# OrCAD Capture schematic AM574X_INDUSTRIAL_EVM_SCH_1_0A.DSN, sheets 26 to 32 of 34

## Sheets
26 Pg17: Gbit Ethernet #0: size C
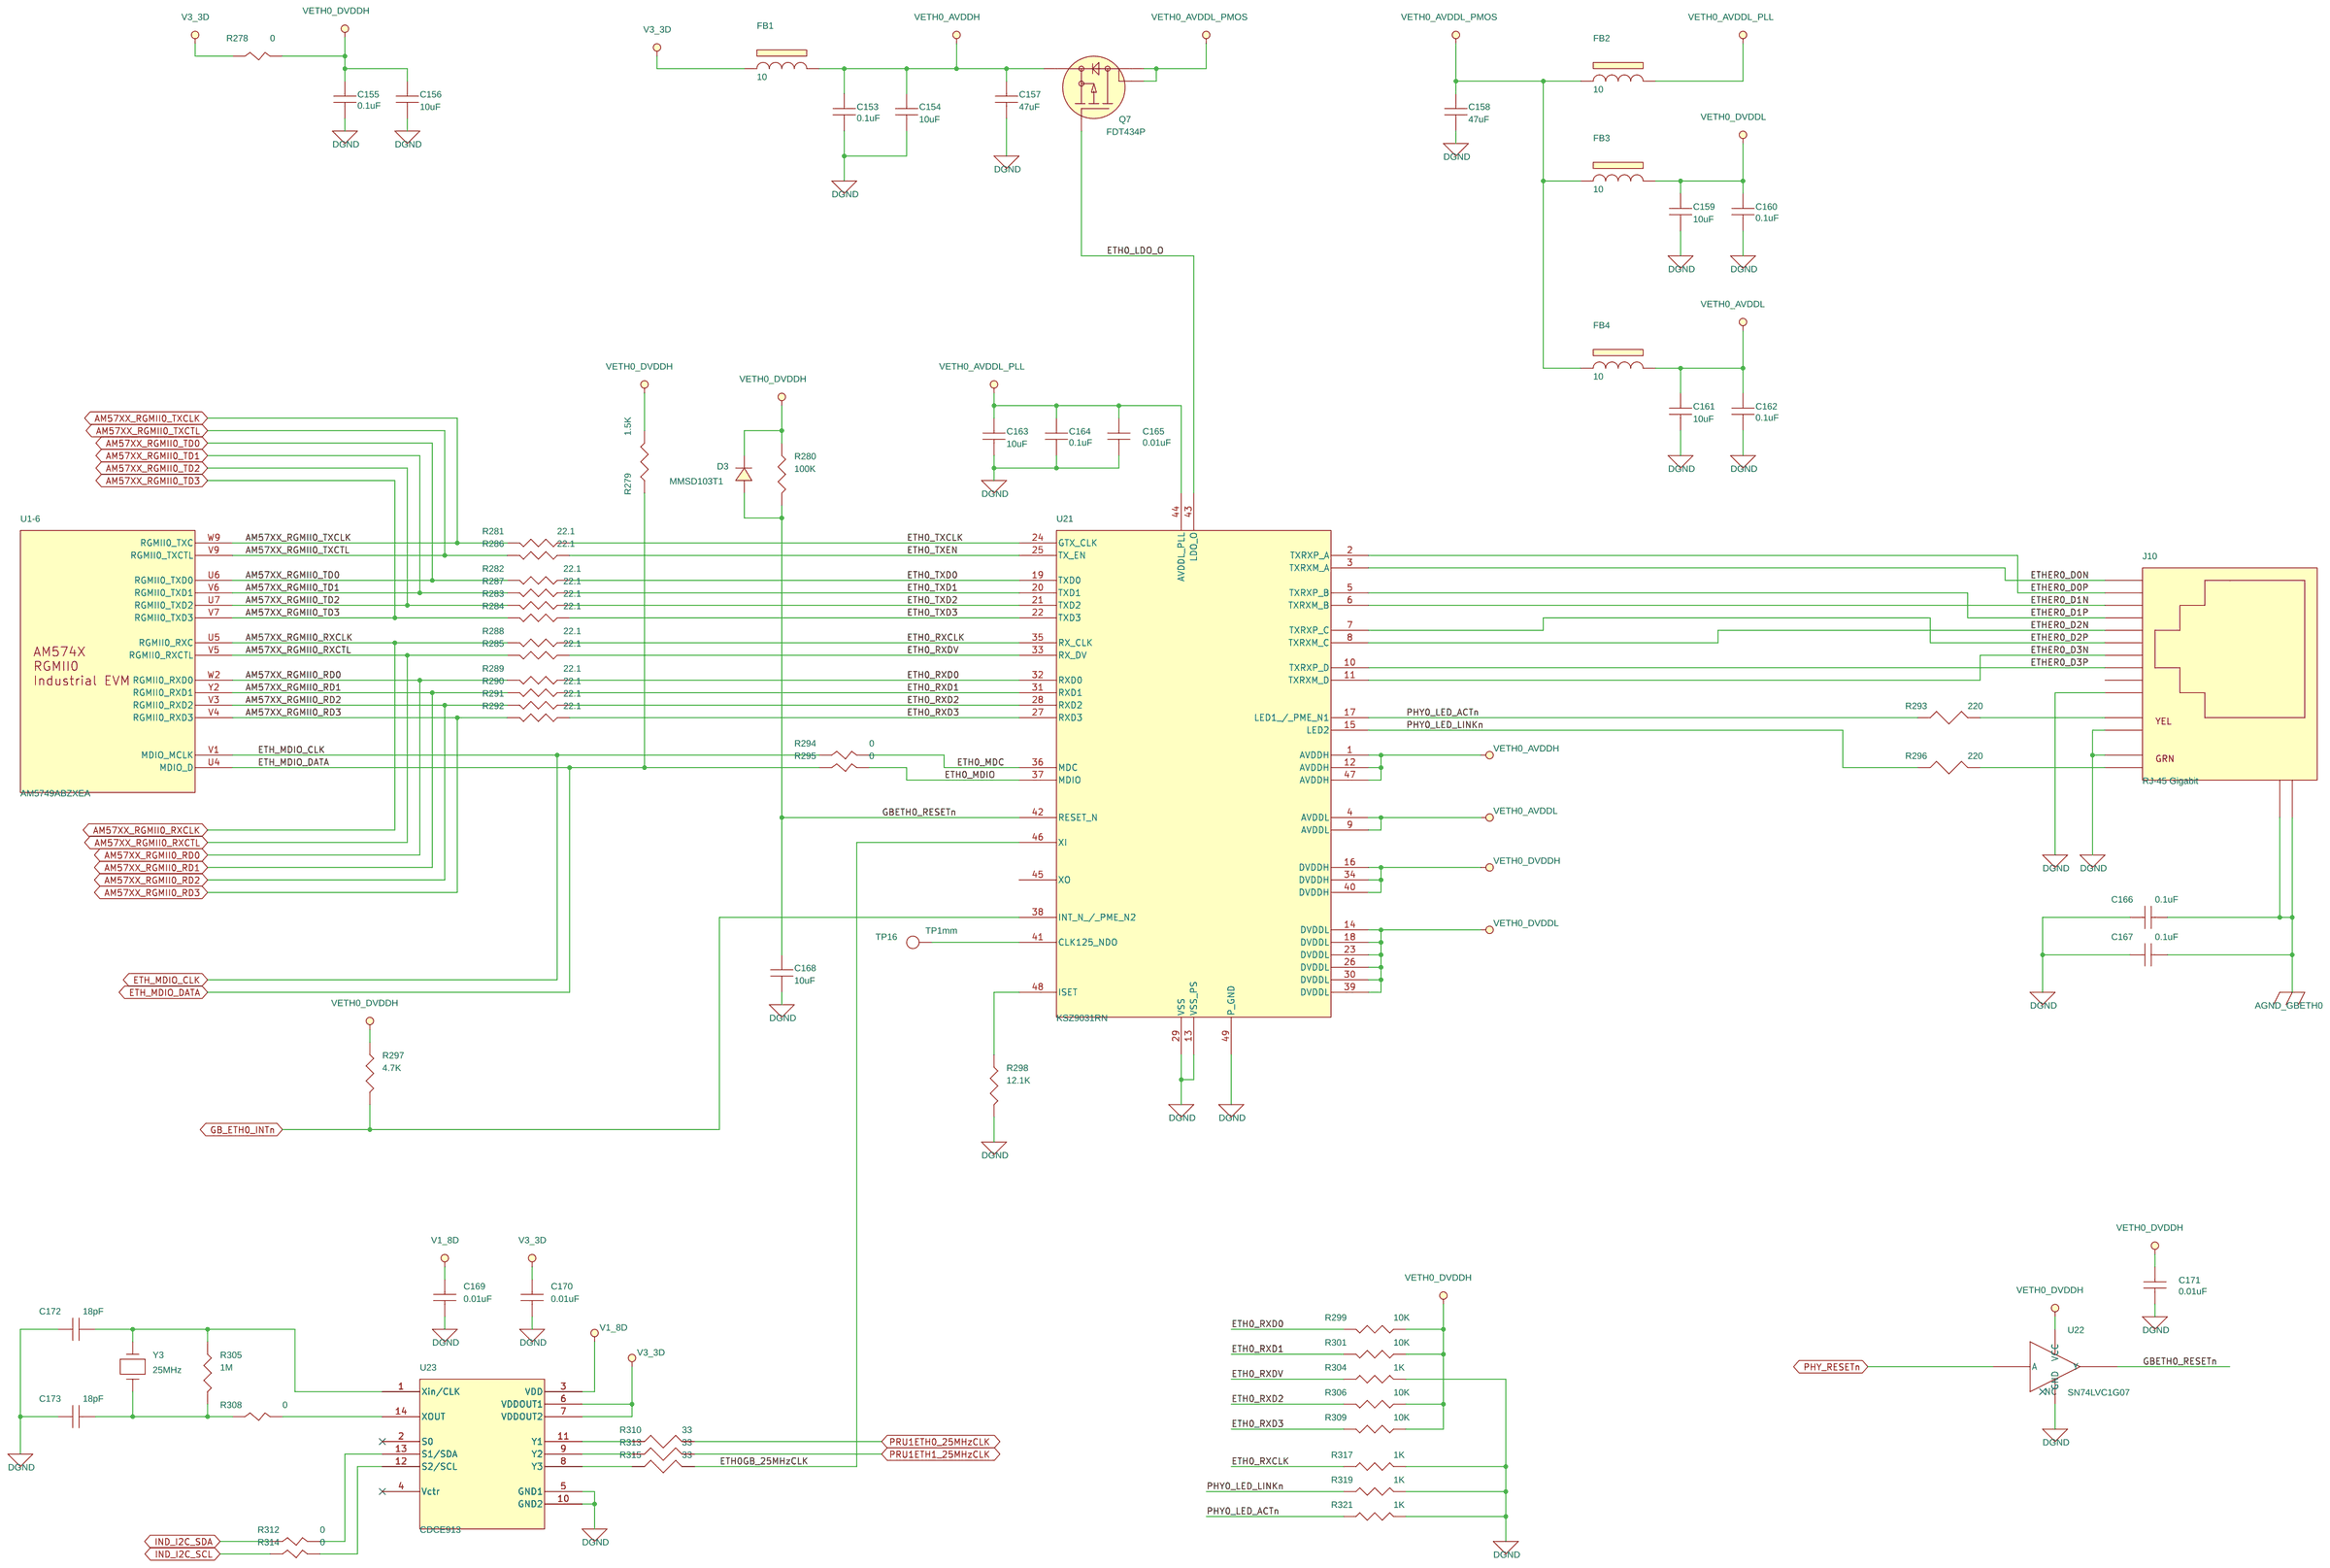
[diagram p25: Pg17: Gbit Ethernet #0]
27 Pg14: ICSS2 Ethernet 1: size C
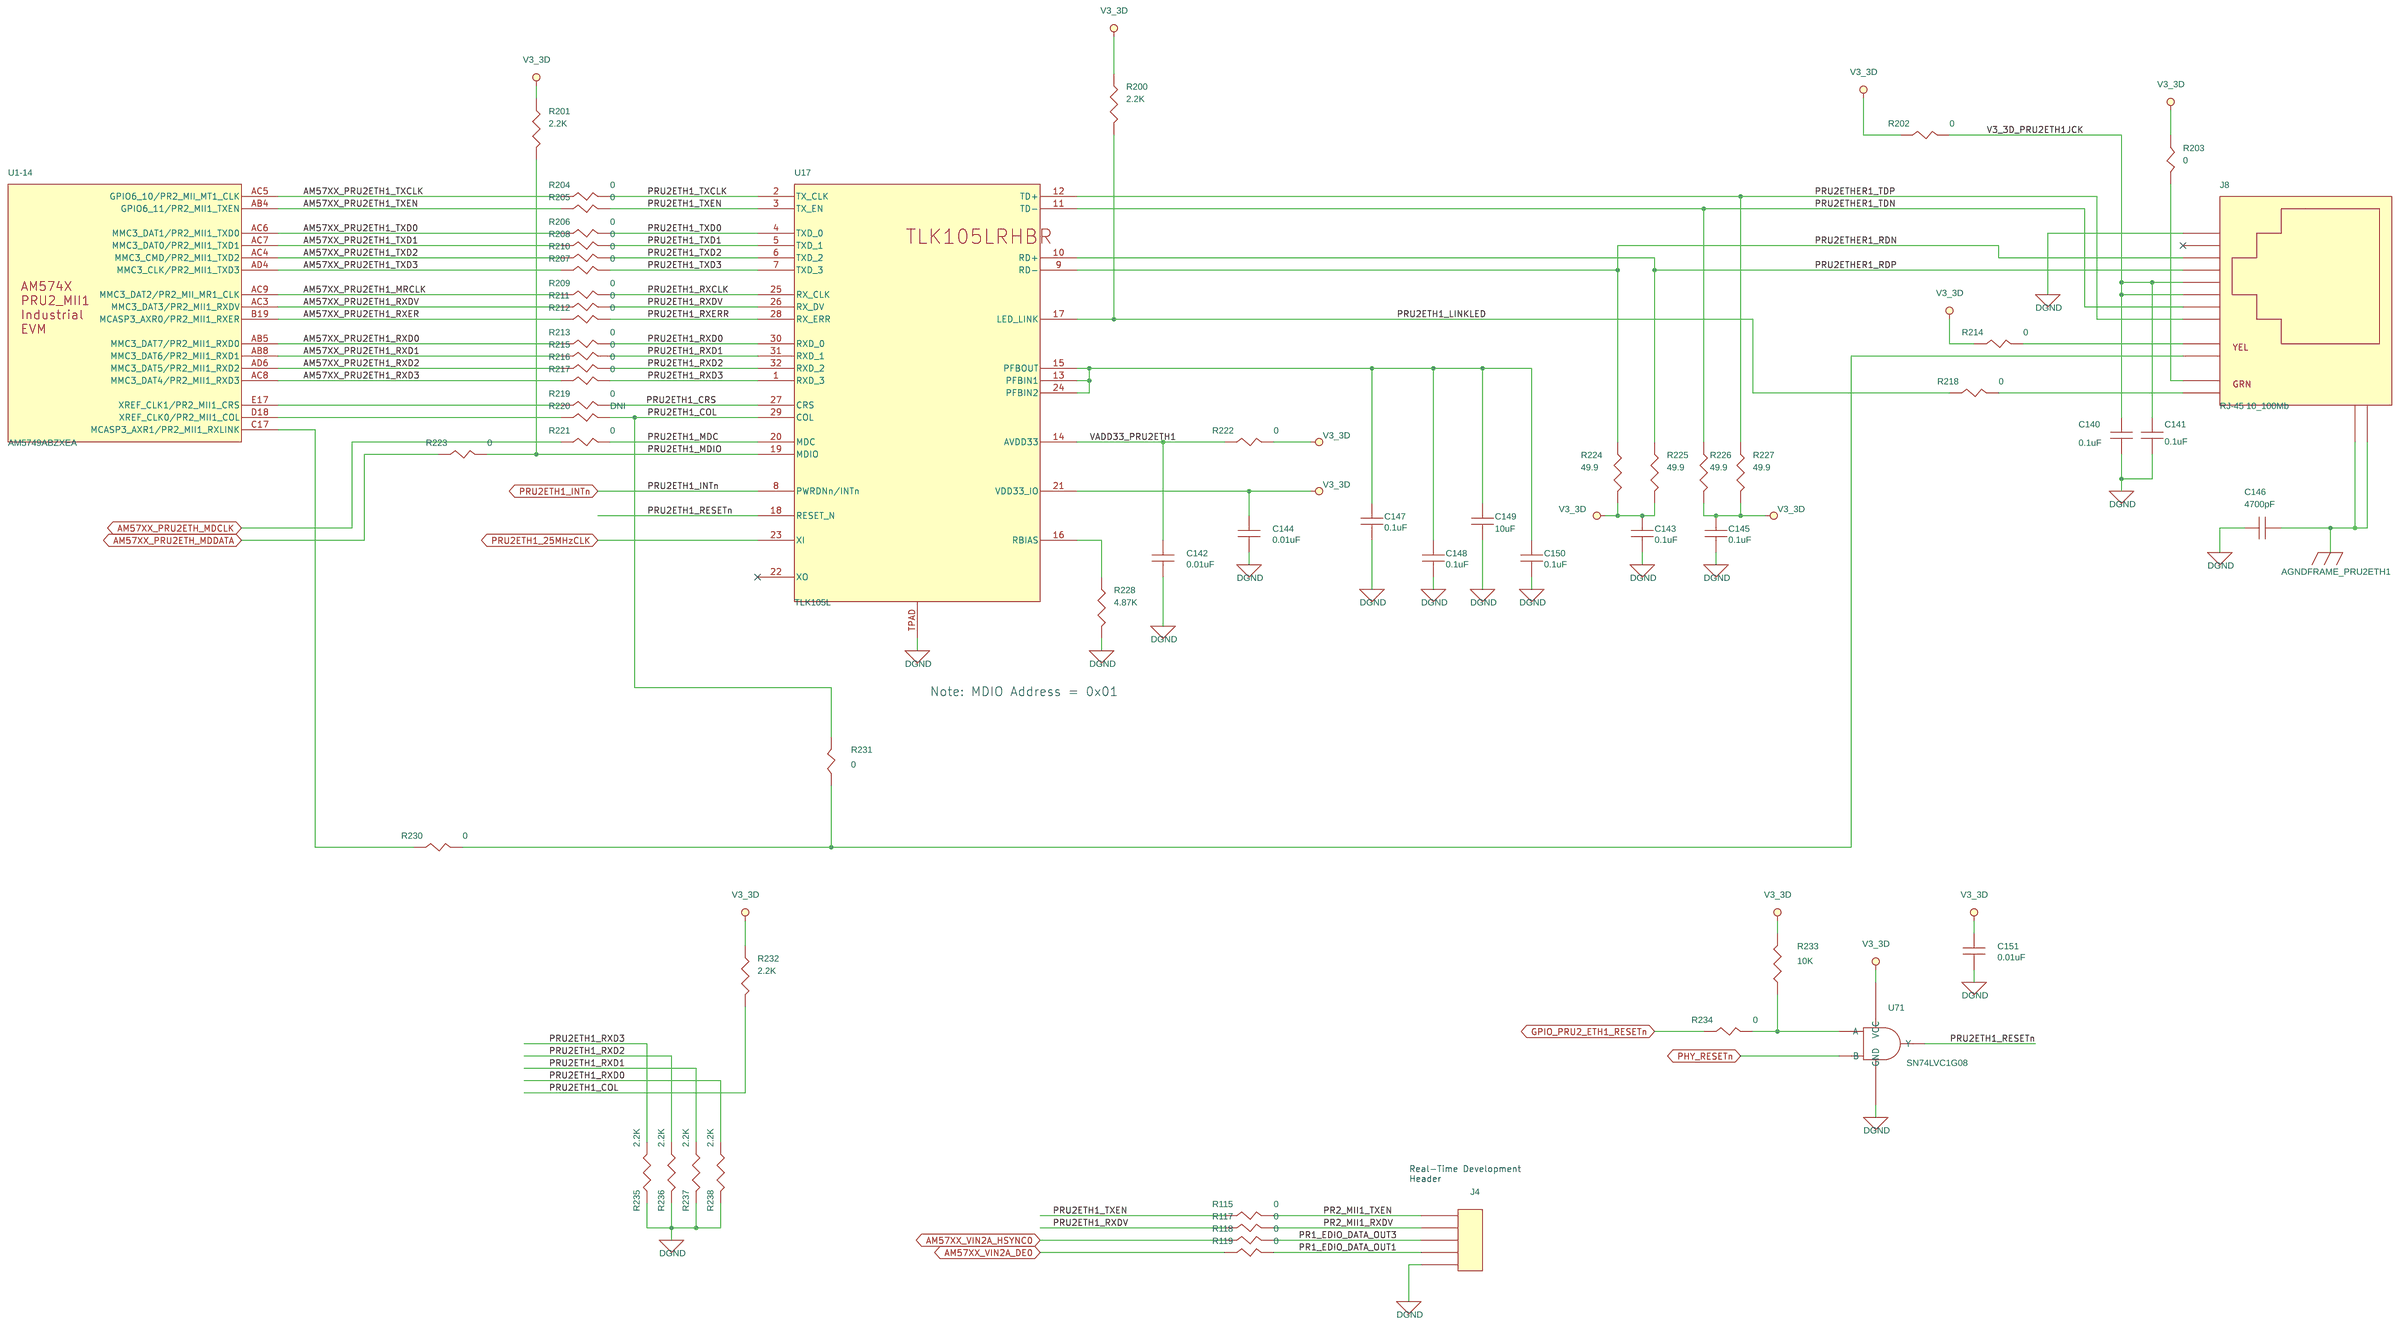
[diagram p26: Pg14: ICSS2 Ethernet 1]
28 Pg18: Gbit Ethernet #1: size C
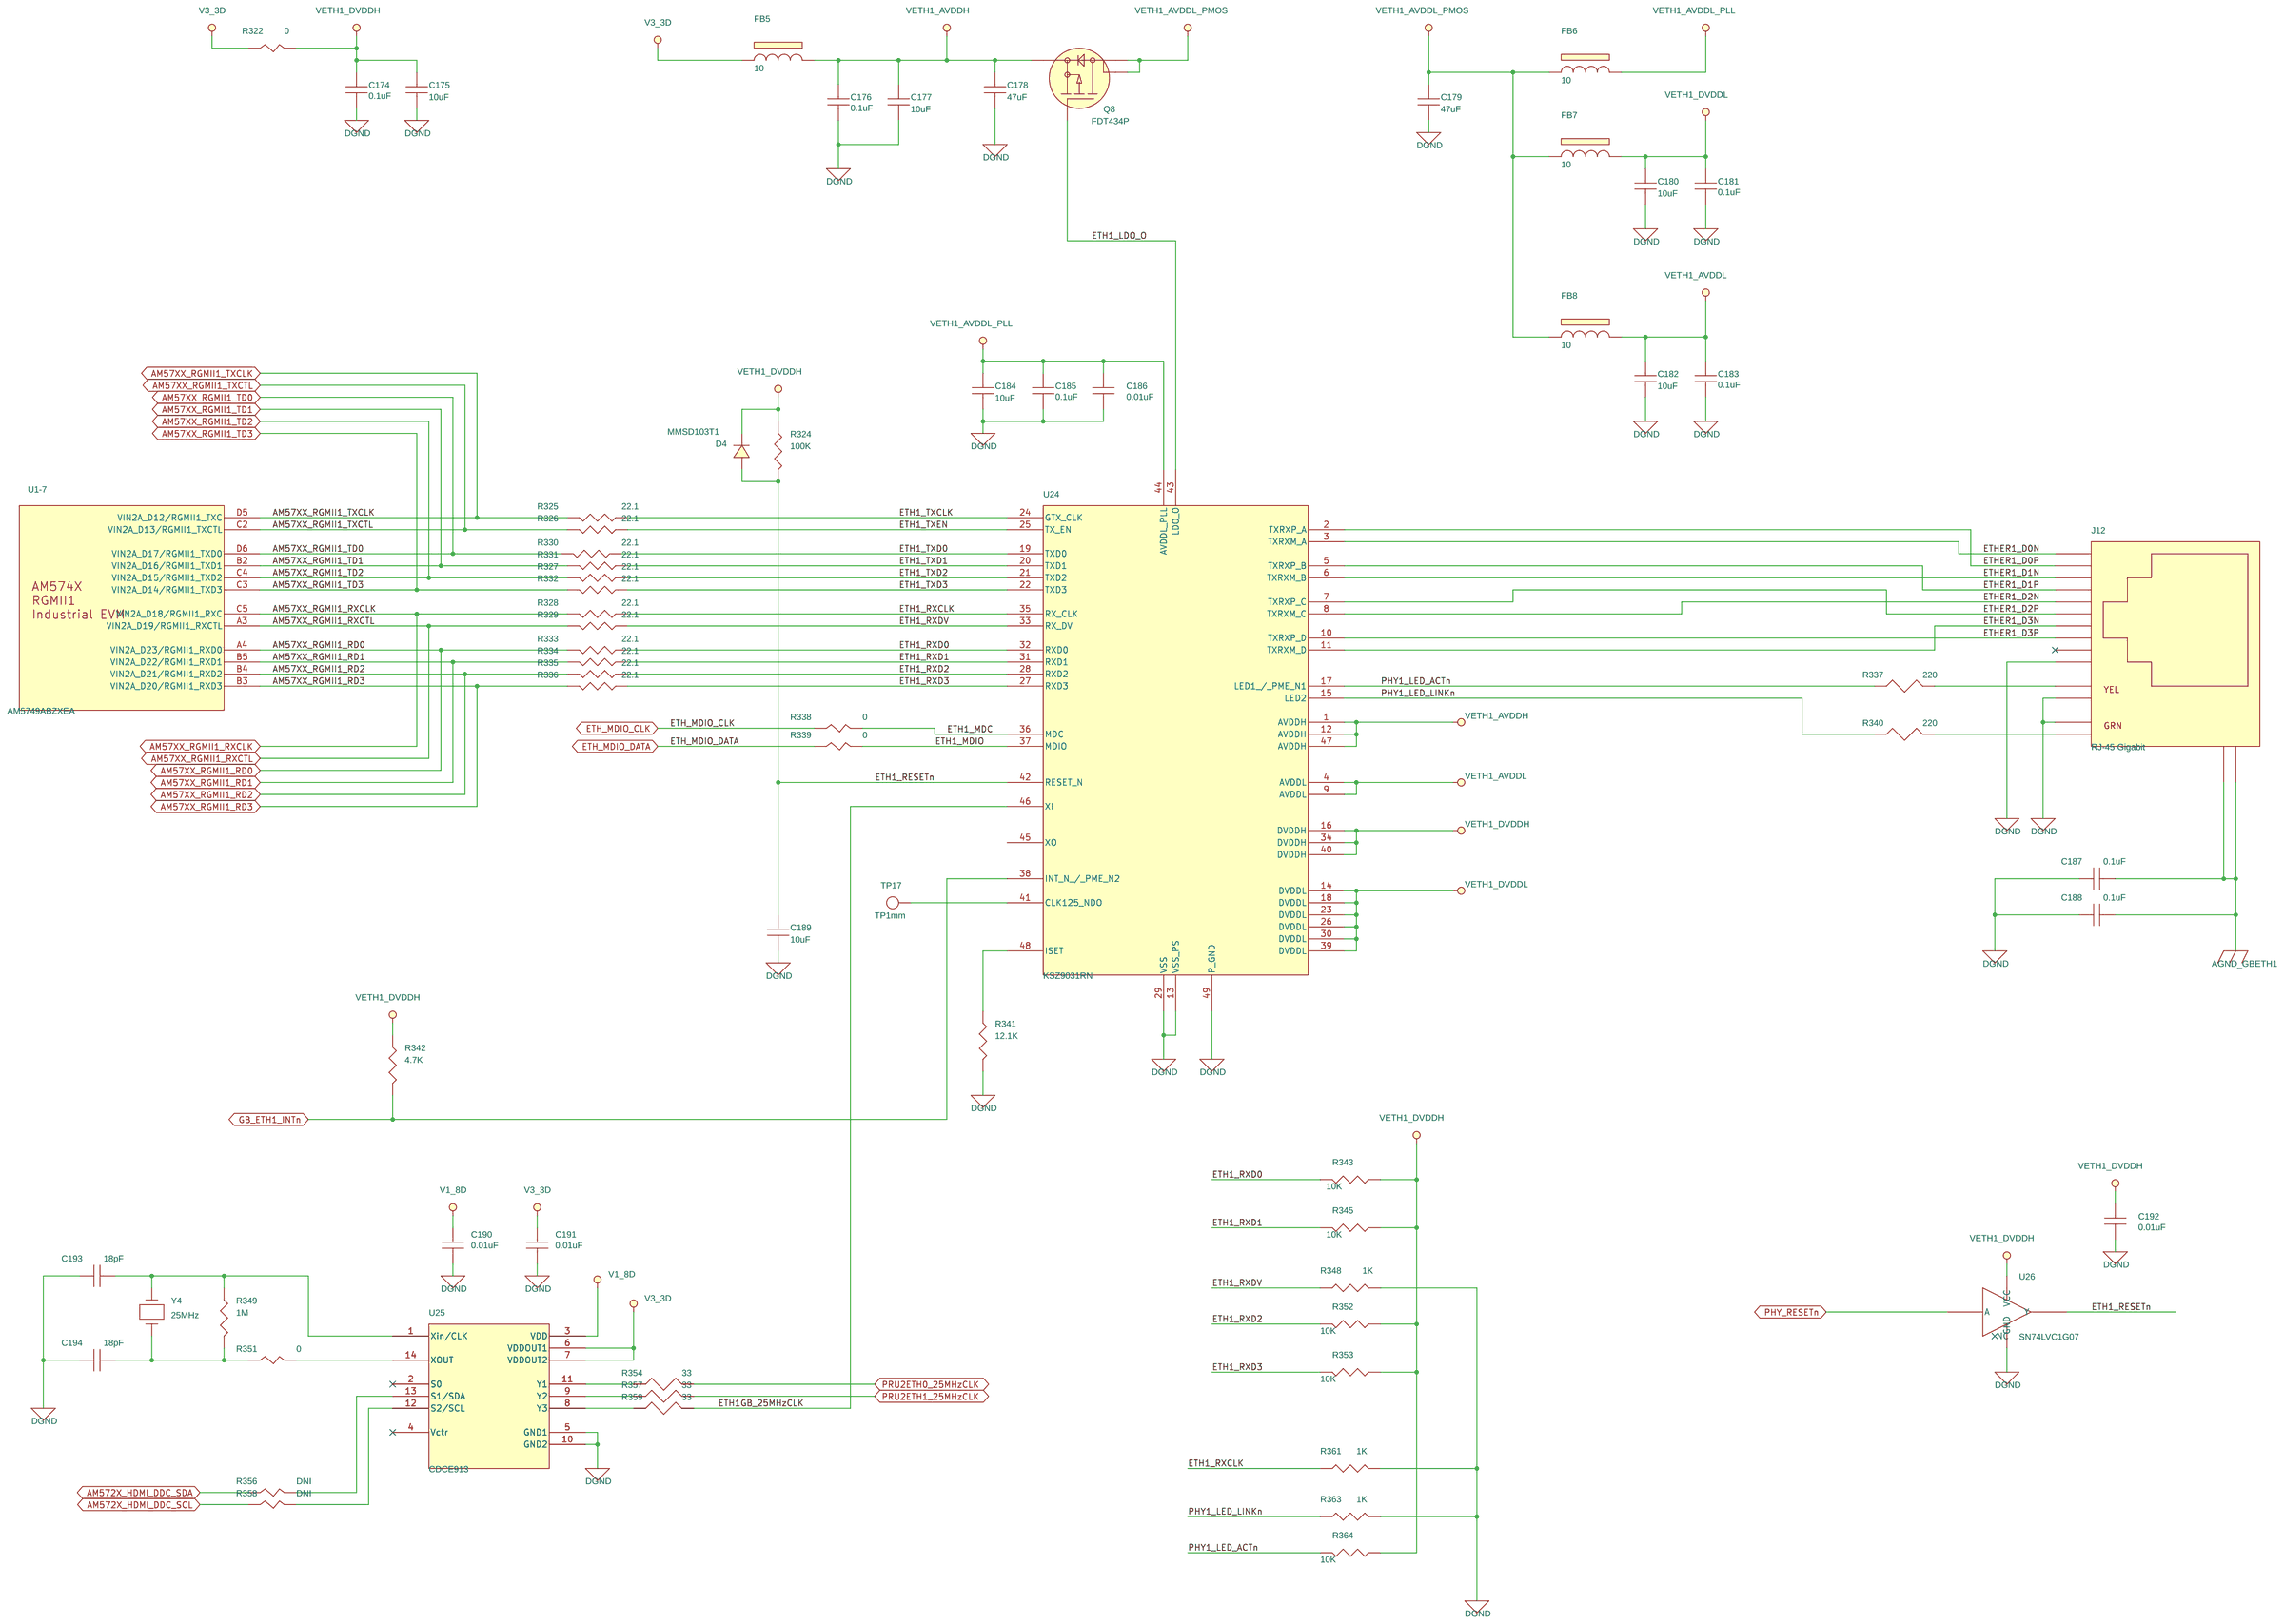
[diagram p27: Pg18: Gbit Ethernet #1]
29 Pg19: SDMMC #1 Interface: size C
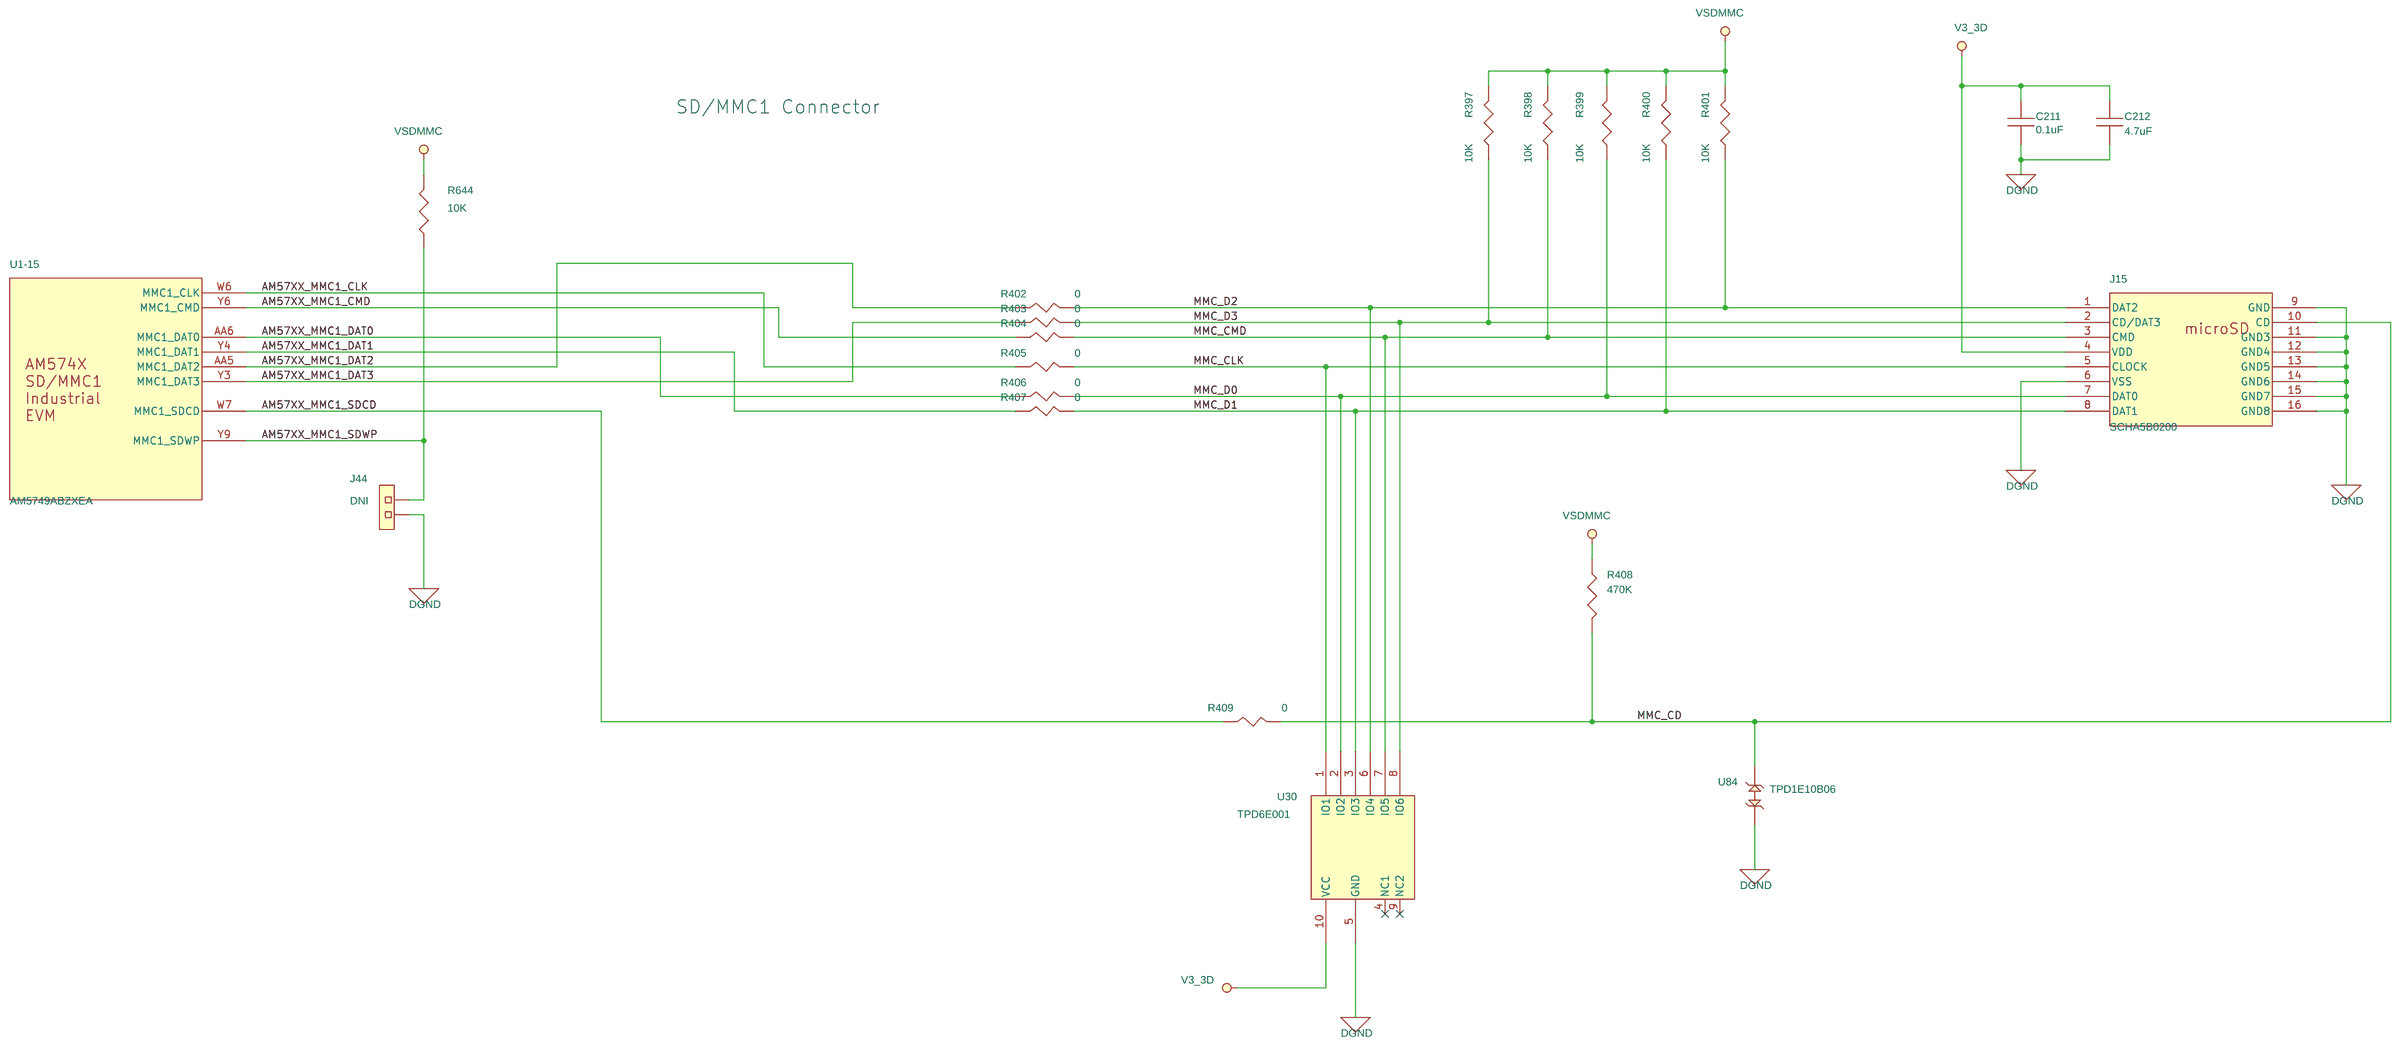
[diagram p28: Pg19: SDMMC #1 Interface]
30 Pg32: RTC & VPP Circuit: size C
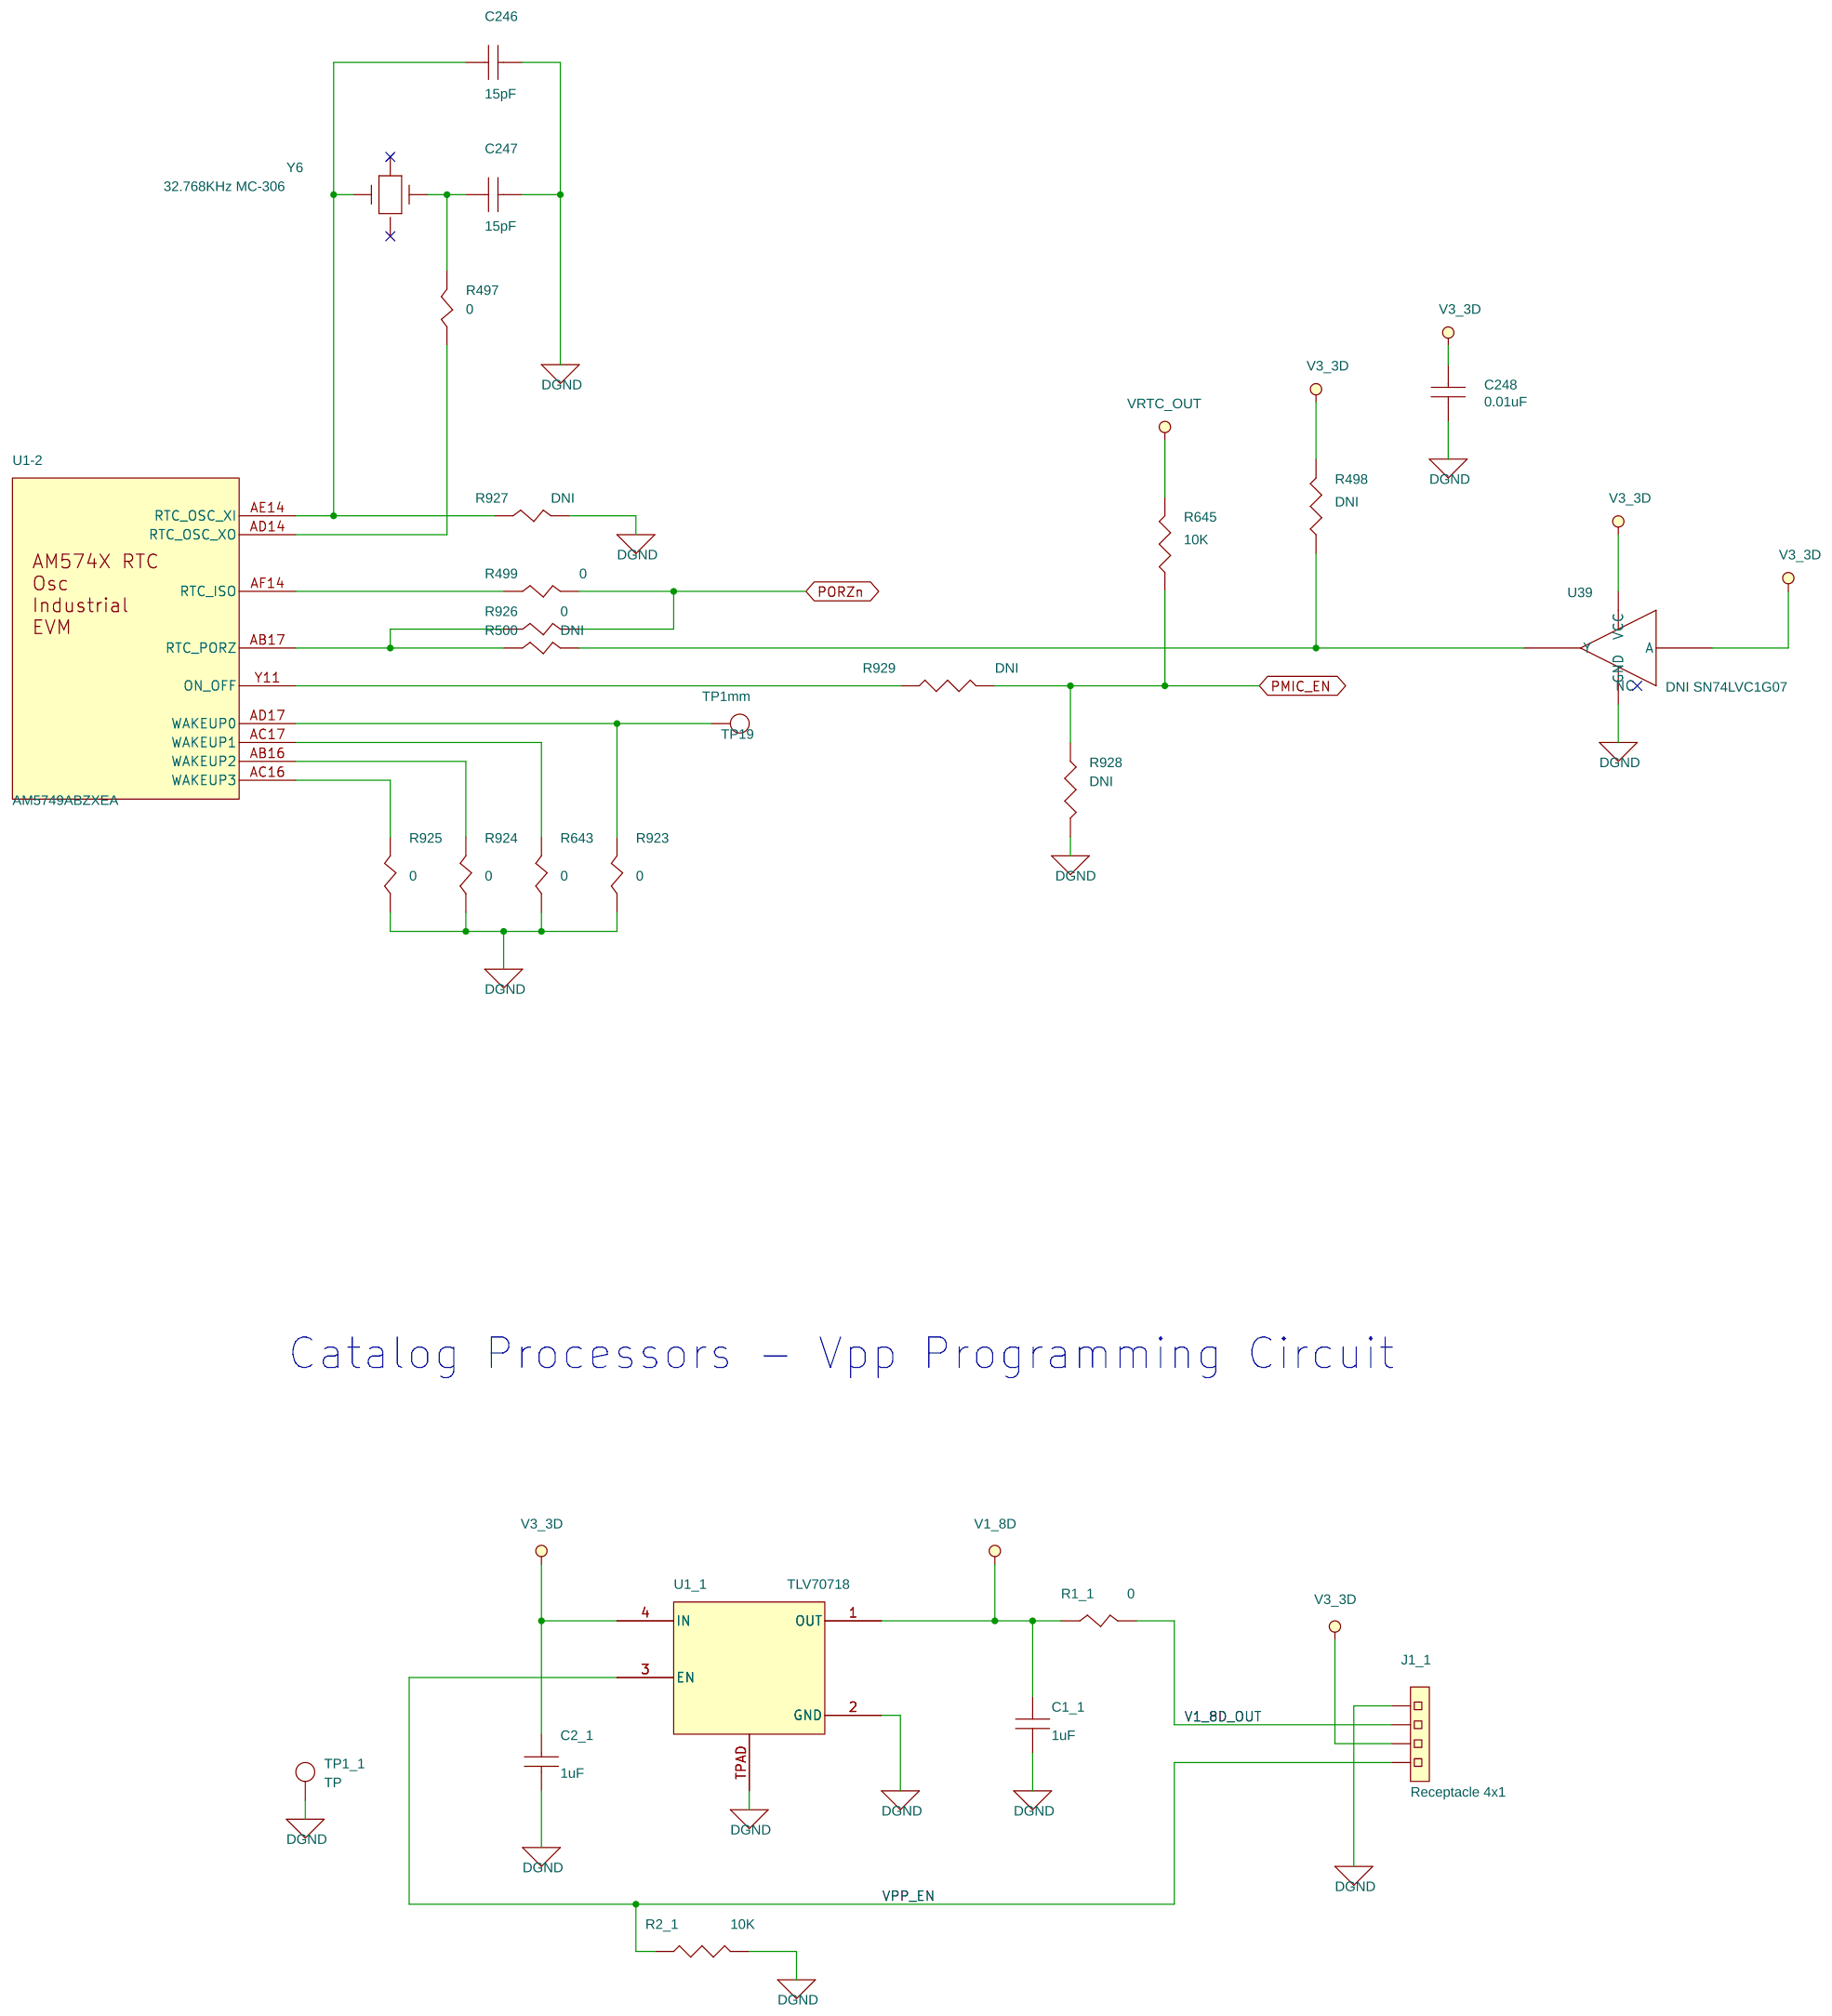
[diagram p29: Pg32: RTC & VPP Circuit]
31 Pg33: Expansion Connector: size C
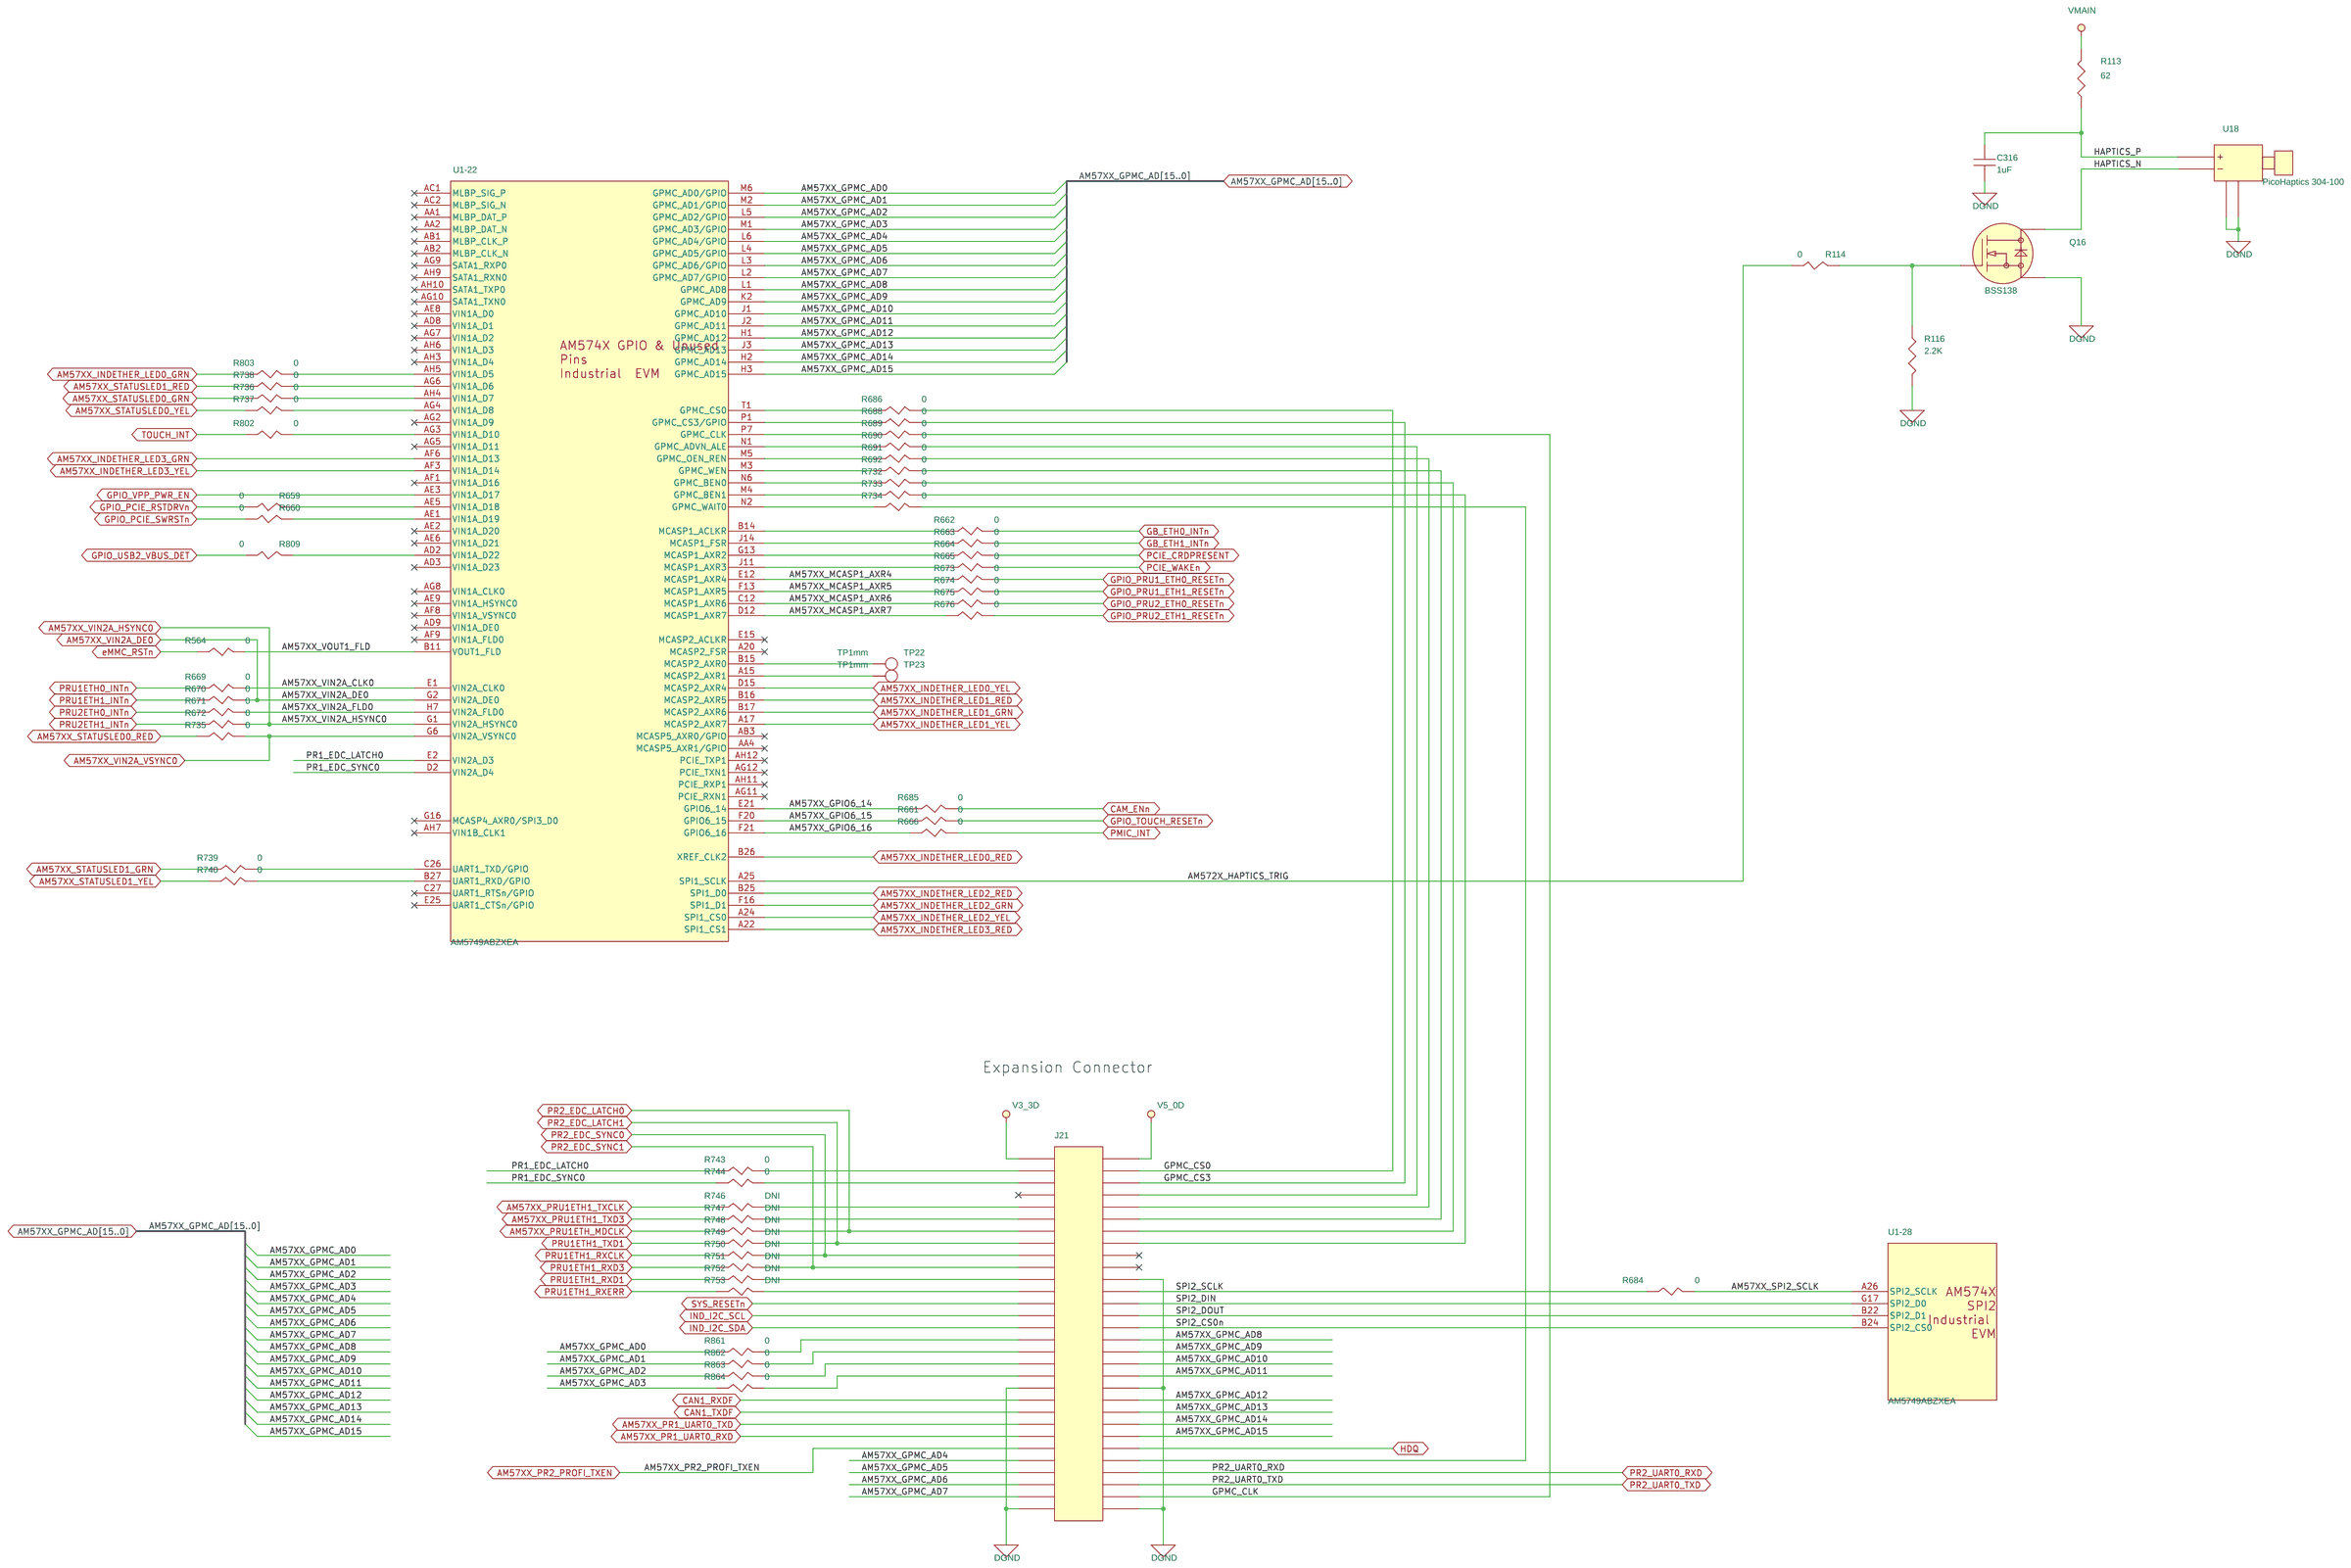
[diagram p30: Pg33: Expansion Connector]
32 Pg02: Processor subsystem: size C
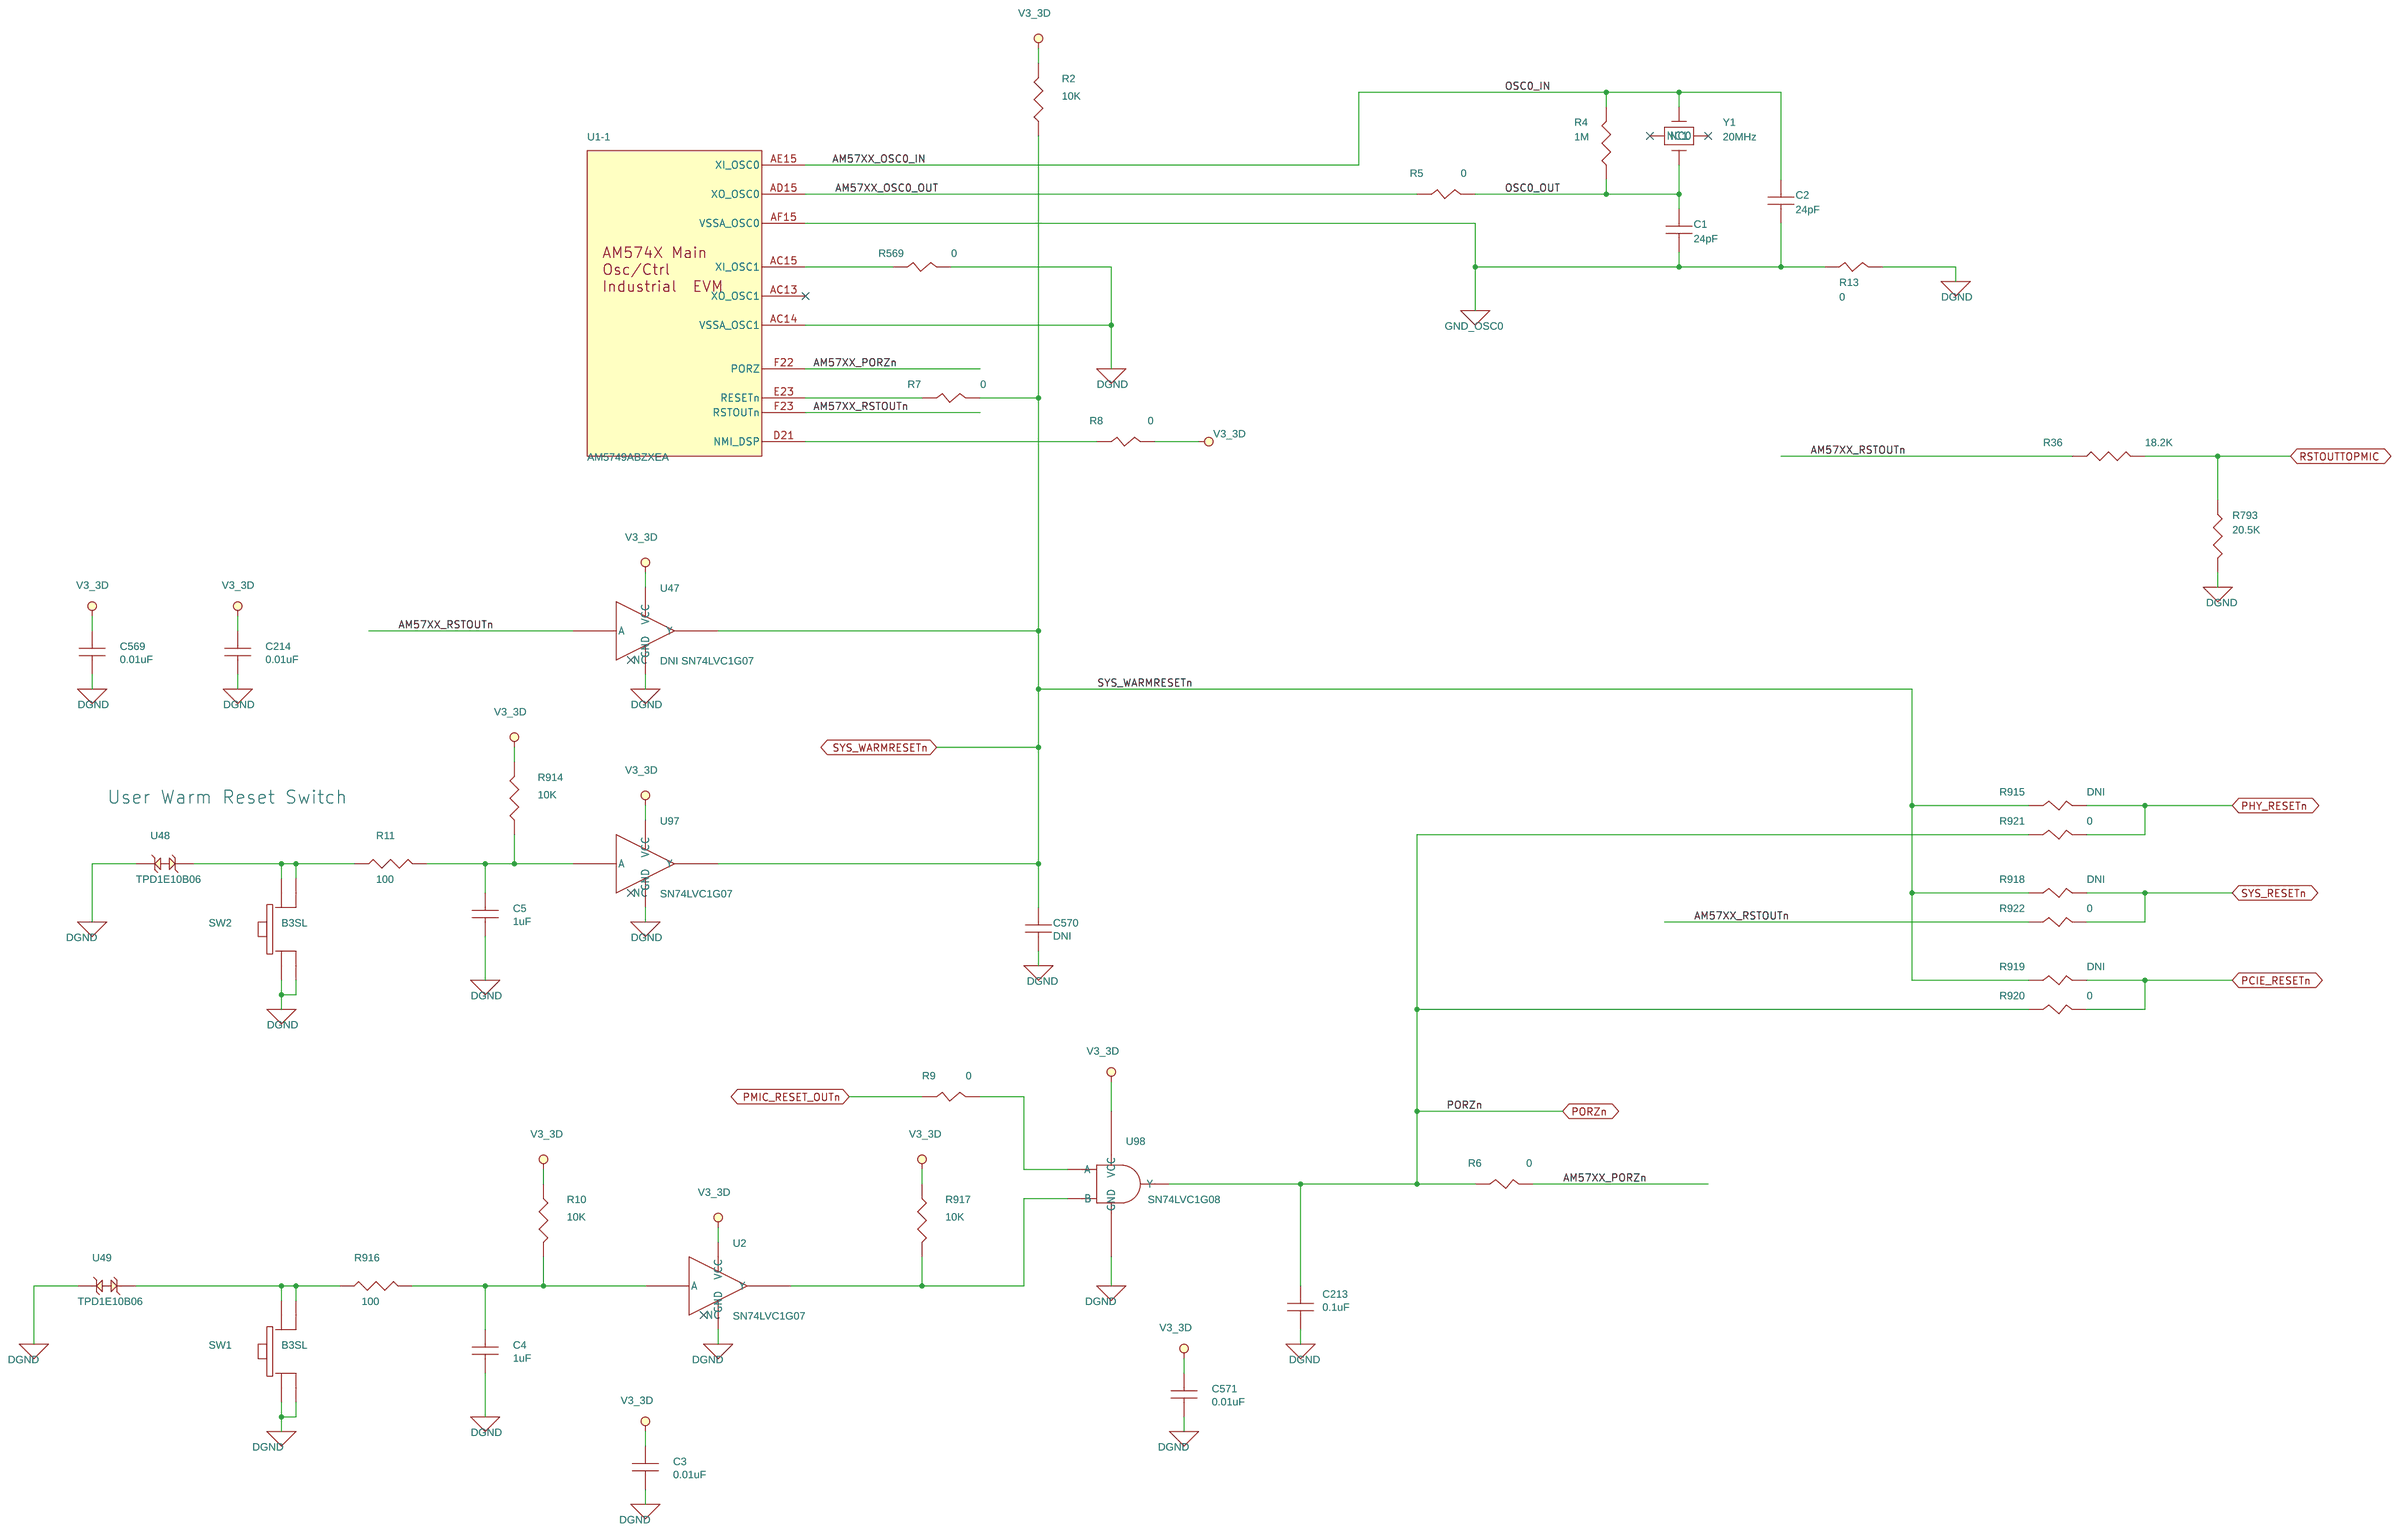
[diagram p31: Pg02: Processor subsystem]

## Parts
sheet Pg02: Processor subsystem
C1  24pF  [SM-7351-CAP-0402]
C2  24pF  [SM-7351-CAP-0402]
C3  0.01uF  [SM-7351-CAP-0402]
C4  1uF  [SM-7351-CAP-0402]
C5  1uF  [SM-7351-CAP-0402]
C213  0.1uF  [SM-7351-CAP-0402]
C214  0.01uF  [SM-7351-CAP-0402]
C569  0.01uF  [SM-7351-CAP-0402]
C570  DNI  [SM-7351-CAP-0402]
C571  0.01uF  [SM-7351-CAP-0402]
R2  10K  [SM-7351-RES-0402]
R4  1M  [SM-7351-RES-0402]
R5  0  [SM-7351-RES-0402]
R6  0  [SM-7351-RES-0402]
R7  0  [SM-7351-RES-0402]
R8  0  [SM-7351-RES-0402]
R9  0  [SM-7351-RES-0402]
R10  10K  [SM-7351-RES-0402]
R11  100  [SM-7351-RES-0402]
R13  0  [SM-7351-RES-0402]
R36  18.2K  [SM-7351-RES-0402]
R569  0  [SM-7351-RES-0402]
R793  20.5K  [SM-7351-RES-0402]
R914  10K  [SM-7351-RES-0402]
R915  DNI  [SM-7351-RES-0402]
R916  100  [SM-7351-RES-0402]
R917  10K  [SM-7351-RES-0402]
R918  DNI  [SM-7351-RES-0402]
R919  DNI  [SM-7351-RES-0402]
R920  0  [SM-7351-RES-0402]
R921  0  [SM-7351-RES-0402]
R922  0  [SM-7351-RES-0402]
SW1  B3SL  [SW_B3SL-1022P]
SW2  B3SL  [SW_B3SL-1022P]
U2  SN74LVC1G07  [u_5_dck]
U47  DNI SN74LVC1G07  [u_5_dck]
U48  TPD1E10B06  [tpd1e10b06-2l]
U49  TPD1E10B06  [tpd1e10b06-2l]
U97  SN74LVC1G07  [u_5_dck]
U98  SN74LVC1G08  [sm-so-sc70-5]
Y1  20MHz  [XTAL2X3-30M]
sheet Pg14: ICSS2 Ethernet 1
C140  0.1uF  [SM-7351-CAP-0402]
C141  0.1uF  [SM-7351-CAP-0402]
C142  0.01uF  [SM-7351-CAP-0402]
C143  0.1uF  [SM-7351-CAP-0402]
C144  0.01uF  [SM-7351-CAP-0402]
C145  0.1uF  [SM-7351-CAP-0402]
C146  4700pF  [SM-7351-CAP-0402]
C147  0.1uF  [SM-7351-CAP-0402]
C148  0.1uF  [SM-7351-CAP-0402]
C149  10uF  [SM-7351-CAP-0805]
C150  0.1uF  [SM-7351-CAP-0402]
C151  0.01uF  [SM-7351-CAP-0402]
J4  HEADER 5  [HEADER_5X1]
J8  RJ-45 10_100Mb  [CNRJ45-1X1WLED]
R115  0  [SM-7351-RES-0402]
R117  0  [SM-7351-RES-0402]
R118  0  [SM-7351-RES-0402]
R119  0  [SM-7351-RES-0402]
R200  2.2K  [sm-7351-res-0402]
R201  2.2K  [sm-7351-res-0402]
R202  0  [SM-7351-RES-0402]
R203  0  [SM-7351-RES-0402]
R204  0  [SM-7351-RES-0402]
R205  0  [SM-7351-RES-0402]
R206  0  [SM-7351-RES-0402]
R207  0  [SM-7351-RES-0402]
R208  0  [SM-7351-RES-0402]
R209  0  [SM-7351-RES-0402]
R210  0  [SM-7351-RES-0402]
R211  0  [SM-7351-RES-0402]
R212  0  [SM-7351-RES-0402]
R213  0  [SM-7351-RES-0402]
R214  0  [SM-7351-RES-0402]
R215  0  [SM-7351-RES-0402]
R216  0  [SM-7351-RES-0402]
R217  0  [SM-7351-RES-0402]
R218  0  [SM-7351-RES-0603]
R219  0  [SM-7351-RES-0402]
R220  DNI  [SM-7351-RES-0402]
R221  0  [SM-7351-RES-0402]
R222  0  [SM-7351-RES-0603]
R223  0  [SM-7351-RES-0402]
R224  49.9  [SM-7351-RES-0402]
R225  49.9  [SM-7351-RES-0402]
R226  49.9  [SM-7351-RES-0402]
R227  49.9  [SM-7351-RES-0402]
R228  4.87K  [SM-7351-RES-0402]
R230  0  [SM-7351-RES-0402]
R231  0  [SM-7351-RES-0402]
R232  2.2K  [sm-7351-res-0402]
R233  10K  [SM-7351-RES-0402]
R234  0  [SM-7351-RES-0402]
R235  2.2K  [sm-7351-res-0402]
R236  2.2K  [sm-7351-res-0402]
R237  2.2K  [sm-7351-res-0402]
R238  2.2K  [sm-7351-res-0402]
U17  TLK105L  [qfn5x5-32-39m]
U71  SN74LVC1G08  [sm-so-sc70-5]
sheet Pg17: Gbit Ethernet #0
C153  0.1uF  [SM-7351-CAP-0402]
C154  10uF  [SM-7351-CAP-0805]
C155  0.1uF  [SM-7351-CAP-0402]
C156  10uF  [SM-7351-CAP-0805]
C157  47uF  [SM-7351-CAP-1206]
C158  47uF  [SM-7351-CAP-1206]
C159  10uF  [SM-7351-CAP-0805]
C160  0.1uF  [SM-7351-CAP-0402]
C161  10uF  [SM-7351-CAP-0805]
C162  0.1uF  [SM-7351-CAP-0402]
C163  10uF  [SM-7351-CAP-0805]
C164  0.1uF  [SM-7351-CAP-0402]
C165  0.01uF  [SM-7351-CAP-0402]
C166  0.1uF  [SM-7351-CAP-0402]
C167  0.1uF  [SM-7351-CAP-0402]
C168  10uF  [SM-7351-CAP-0805]
C169  0.01uF  [SM-7351-CAP-0402]
C170  0.01uF  [SM-7351-CAP-0402]
C171  0.01uF  [SM-7351-CAP-0402]
C172  18pF  [SM-7351-CAP-0402]
C173  18pF  [SM-7351-CAP-0402]
D3  MMSD103T1  [sod-123]
FB1  10  [HF70ACB201209]
FB2  10  [HF70ACB201209]
FB3  10  [HF70ACB201209]
FB4  10  [HF70ACB201209]
J10  RJ-45 Gigabit  [CNRJ45-1X1WLED-598M]
Q7  FDT434P  [SOT223-4]
R278  0  [SM-7351-RES-0603]
R279  1.5K  [SM-7351-RES-0402]
R280  100K  [SM-7351-RES-0402]
R281  22.1  [SM-7351-RES-0402]
R282  22.1  [SM-7351-RES-0402]
R283  22.1  [SM-7351-RES-0402]
R284  22.1  [SM-7351-RES-0402]
R285  22.1  [SM-7351-RES-0402]
R286  22.1  [SM-7351-RES-0402]
R287  22.1  [SM-7351-RES-0402]
R288  22.1  [SM-7351-RES-0402]
R289  22.1  [SM-7351-RES-0402]
R290  22.1  [SM-7351-RES-0402]
R291  22.1  [SM-7351-RES-0402]
R292  22.1  [SM-7351-RES-0402]
R293  220  [SM-7351-RES-0402]
R294  0  [SM-7351-RES-0402]
R295  0  [SM-7351-RES-0402]
R296  220  [SM-7351-RES-0402]
R297  4.7K  [SM-7351-RES-0402]
R298  12.1K  [SM-7351-RES-0402]
R299  10K  [SM-7351-RES-0402]
R301  10K  [SM-7351-RES-0402]
R304  1K  [SM-7351-RES-0402]
R305  1M  [SM-7351-RES-0402]
R306  10K  [SM-7351-RES-0402]
R308  0  [SM-7351-RES-0402]
R309  10K  [SM-7351-RES-0402]
R310  33  [SM-7351-RES-0402]
R312  0  [SM-7351-RES-0402]
R313  33  [SM-7351-RES-0402]
R314  0  [SM-7351-RES-0402]
R315  33  [SM-7351-RES-0402]
R317  1K  [SM-7351-RES-0402]
R319  1K  [SM-7351-RES-0402]
R321  1K  [SM-7351-RES-0402]
TP16  TP1mm  [tp_smd1mmcircle]
U21  KSZ9031RN  [qfn7x7-48]
U22  SN74LVC1G07  [u_5_dck]
U23  CDCE913  [TSSOP5X4-14-47M]
Y3  25MHz  [SM_OSC_ABM3]
sheet Pg18: Gbit Ethernet #1
C174  0.1uF  [SM-7351-CAP-0402]
C175  10uF  [SM-7351-CAP-0805]
C176  0.1uF  [SM-7351-CAP-0402]
C177  10uF  [SM-7351-CAP-0805]
C178  47uF  [SM-7351-CAP-1206]
C179  47uF  [SM-7351-CAP-1206]
C180  10uF  [SM-7351-CAP-0805]
C181  0.1uF  [SM-7351-CAP-0402]
C182  10uF  [SM-7351-CAP-0805]
C183  0.1uF  [SM-7351-CAP-0402]
C184  10uF  [SM-7351-CAP-0805]
C185  0.1uF  [SM-7351-CAP-0402]
C186  0.01uF  [SM-7351-CAP-0402]
C187  0.1uF  [SM-7351-CAP-0402]
C188  0.1uF  [SM-7351-CAP-0402]
C189  10uF  [SM-7351-CAP-0805]
C190  0.01uF  [SM-7351-CAP-0402]
C191  0.01uF  [SM-7351-CAP-0402]
C192  0.01uF  [SM-7351-CAP-0402]
C193  18pF  [SM-7351-CAP-0402]
C194  18pF  [SM-7351-CAP-0402]
D4  MMSD103T1  [sod-123]
FB5  10  [HF70ACB201209]
FB6  10  [HF70ACB201209]
FB7  10  [HF70ACB201209]
FB8  10  [HF70ACB201209]
J12  RJ-45 Gigabit  [CNRJ45-1X1WLED-598M]
Q8  FDT434P  [SOT223-4]
R322  0  [SM-7351-RES-0603]
R324  100K  [SM-7351-RES-0402]
R325  22.1  [SM-7351-RES-0402]
R326  22.1  [SM-7351-RES-0402]
R327  22.1  [SM-7351-RES-0402]
R328  22.1  [SM-7351-RES-0402]
R329  22.1  [SM-7351-RES-0402]
R330  22.1  [SM-7351-RES-0402]
R331  22.1  [SM-7351-RES-0402]
R332  22.1  [SM-7351-RES-0402]
R333  22.1  [SM-7351-RES-0402]
R334  22.1  [SM-7351-RES-0402]
R335  22.1  [SM-7351-RES-0402]
R336  22.1  [SM-7351-RES-0402]
R337  220  [SM-7351-RES-0402]
R338  0  [SM-7351-RES-0402]
R339  0  [SM-7351-RES-0402]
R340  220  [SM-7351-RES-0402]
R341  12.1K  [SM-7351-RES-0402]
R342  4.7K  [SM-7351-RES-0402]
R343  10K  [SM-7351-RES-0402]
R345  10K  [SM-7351-RES-0402]
R348  1K  [SM-7351-RES-0402]
R349  1M  [SM-7351-RES-0402]
R351  0  [SM-7351-RES-0402]
R352  10K  [SM-7351-RES-0402]
R353  10K  [SM-7351-RES-0402]
R354  33  [SM-7351-RES-0402]
R356  DNI  [SM-7351-RES-0402]
R357  33  [SM-7351-RES-0402]
R358  DNI  [SM-7351-RES-0402]
R359  33  [SM-7351-RES-0402]
R361  1K  [SM-7351-RES-0402]
R363  1K  [SM-7351-RES-0402]
R364  10K  [SM-7351-RES-0402]
TP17  TP1mm  [tp_smd1mmcircle]
U24  KSZ9031RN  [qfn7x7-48]
U25  CDCE913  [TSSOP5X4-14-47M]
U26  SN74LVC1G07  [u_5_dck]
Y4  25MHz  [SM_OSC_ABM3]
sheet Pg19: SDMMC #1 Interface
C211  0.1uF  [SM-7351-CAP-0402]
C212  4.7uF  [SM-7351-CAP-0603]
J15  SCHA5B0200  [SD-MICRO-SCHA5B0300]
J44  DNI  [header_2x1]
R397  10K  [SM-7351-RES-0402]
R398  10K  [SM-7351-RES-0402]
R399  10K  [SM-7351-RES-0402]
R400  10K  [SM-7351-RES-0402]
R401  10K  [SM-7351-RES-0402]
R402  0  [SM-7351-RES-0402]
R403  0  [SM-7351-RES-0402]
R404  0  [SM-7351-RES-0402]
R405  0  [SM-7351-RES-0402]
R406  0  [SM-7351-RES-0402]
R407  0  [SM-7351-RES-0402]
R408  470K  [SM-7351-RES-0402]
R409  0  [SM-7351-RES-0402]
R644  10K  [SM-7351-RES-0402]
U30  TPD6E001  [U_10_RSE]
U84  TPD1E10B06  [tpd1e10b06-2l]
sheet Pg29: Profibus
U1  AM5749ABZXEA  [BGA23X23-760-117M]  (sections -1,-10,-11,-12,-13,-14,-15,-16,-17,-18,-19,-2,-20,-21,-22,-23,-24,-25,-26,-27,-28,-29,-3,-4,-5,-6,-7,-8,-9)
sheet Pg32: RTC & VPP Circuit
C1_1  1uF  [SM-7351-CAP-0603]
C2_1  1uF  [SM-7351-CAP-0603]
C246  15pF  [SM-7351-CAP-0402]
C247  15pF  [SM-7351-CAP-0402]
C248  0.01uF  [SM-7351-CAP-0402]
J1_1  Receptacle 4x1  [HDR4X1RA-108M]
R1_1  0  [SM-7351-RES-0603]
R2_1  10K  [SM-7351-RES-0402]
R497  0  [SM-7351-RES-0402]
R498  DNI  [SM-7351-RES-0402]
R499  0  [SM-7351-RES-0402]
R500  DNI  [SM-7351-RES-0402]
R643  0  [SM-7351-RES-0402]
R645  10K  [SM-7351-RES-0402]
R923  0  [SM-7351-RES-0402]
R924  0  [SM-7351-RES-0402]
R925  0  [SM-7351-RES-0402]
R926  0  [SM-7351-RES-0402]
R927  DNI  [SM-7351-RES-0402]
R928  DNI  [SM-7351-RES-0402]
R929  DNI  [SM-7351-RES-0402]
TP1_1  TP  [TH_TP_5002]
TP19  TP1mm  [tp_smd1mmcircle]
U1_1  TLV70718  [X2SON1X1-4-16M]
U39  DNI SN74LVC1G07  [u_5_dck]
Y6  32.768KHz MC-306  [MC-306]
sheet Pg33: Expansion Connector
C316  1uF  [SM-7351-CAP-0603]
J21  Header_30x2_Female  [HDR2X30-2mm-177m]
Q16  BSS138  [SOT23-3]
R113  62  [sm-7351-res-0402]
R114  0  [SM-7351-RES-0402]
R116  2.2K  [sm-7351-res-0402]
R564  0  [SM-7351-RES-0402]
R659  0  [SM-7351-RES-0402]
R660  0  [SM-7351-RES-0402]
R661  0  [SM-7351-RES-0402]
R662  0  [SM-7351-RES-0402]
R663  0  [SM-7351-RES-0402]
R664  0  [SM-7351-RES-0402]
R665  0  [SM-7351-RES-0402]
R666  0  [SM-7351-RES-0402]
R669  0  [SM-7351-RES-0402]
R670  0  [SM-7351-RES-0402]
R671  0  [SM-7351-RES-0402]
R672  0  [SM-7351-RES-0402]
R673  0  [SM-7351-RES-0402]
R674  0  [SM-7351-RES-0402]
R675  0  [SM-7351-RES-0402]
R676  0  [SM-7351-RES-0402]
R684  0  [SM-7351-RES-0402]
R685  0  [SM-7351-RES-0402]
R686  0  [SM-7351-RES-0402]
R688  0  [SM-7351-RES-0402]
R689  0  [SM-7351-RES-0402]
R690  0  [SM-7351-RES-0402]
R691  0  [SM-7351-RES-0402]
R692  0  [SM-7351-RES-0402]
R732  0  [SM-7351-RES-0402]
R733  0  [SM-7351-RES-0402]
R734  0  [SM-7351-RES-0402]
R735  0  [SM-7351-RES-0402]
R736  0  [SM-7351-RES-0402]
R737  0  [SM-7351-RES-0402]
R738  0  [SM-7351-RES-0402]
R739  0  [SM-7351-RES-0402]
R740  0  [SM-7351-RES-0402]
R743  0  [SM-7351-RES-0402]
R744  0  [SM-7351-RES-0402]
R746  DNI  [SM-7351-RES-0402]
R747  DNI  [SM-7351-RES-0402]
R748  DNI  [SM-7351-RES-0402]
R749  DNI  [SM-7351-RES-0402]
R750  DNI  [SM-7351-RES-0402]
R751  DNI  [SM-7351-RES-0402]
R752  DNI  [SM-7351-RES-0402]
R753  DNI  [SM-7351-RES-0402]
R802  0  [SM-7351-RES-0402]
R803  0  [SM-7351-RES-0402]
R809  0  [SM-7351-RES-0402]
R861  0  [SM-7351-RES-0402]
R862  0  [SM-7351-RES-0402]
R863  0  [SM-7351-RES-0402]
R864  0  [SM-7351-RES-0402]
TP22  TP1mm  [tp_smd1mmcircle]
TP23  TP1mm  [tp_smd1mmcircle]
U18  PicoHaptics 304-100  [pico_304-100]

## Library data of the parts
C1 C2 = 1C_24pFCapacitor50V5%SMD0402
C3 C142 C144 C151 C165 C169-C171 C186 C190-C192 C214 C248 C569 C571 = 1C_0.01uFCapacitor16V10%0402
C4 C5 = GRT155R61E105KE01D: DescriptiveText: CAP, CER, 1 UF, 10%, 25V, X5R, 0402; Mfr: MURATA
C140 C141 C143 C145 C147 C148 C150 C153 C155 C160 C162 C164 C174 C176 C181 C183 C185 C211 C213 C570 = C0402C104J4RACTU: DescriptiveText: CAP, CER, 0.1 uF, 16V, 5%, X7R, 0402; Mfr: KEMET
R2 R10 R233 R299 R301 R306 R309 R343 R345 R352 R353 R364 R397-R401 R498 R644 R645 R914 R917 = RMCF0402FT10K0: DescriptiveText: RES, THICK FILM,10K OHM, 1%, 0.063W, SMT0402; Mfr: STACKPOLE ELECTRONICS
R4 R305 R349 = 1MOhmResistor1_16W0402
R5-R9 R13 R114 R115 R117-R119 R202-R217 R219-R221 R223 R230 R231 R234 R294 R295 R308 R312 R314 R338 R339 R351 R356 R358 R402-R407 R409 R497 R499 R500 R564 R569 R643 R659-R666 R669-R676 R684-R686 R688-R692 R732-R740 R743 R744 R746-R753 R802 R803 R809 R861-R864 R915 R918-R927 = 1R_ZeroOhmResistor1_16W0402
R11 R916 = 1R_100ohm1_16W1%SMD0402: Cost100: 0.02; DescriptiveText: Resistor 100ohm 1/10W 1% 0402; Mfr: Panasonic; MfrNum: ERJ-2RKF1000X; PartName: 100ohm1/10W1%0402; TIIntPartnumber: 1R0246
R36 R929 = 1R_18.2Kohm1_16W1%smd0402
R793 R928 = 1R_20.5Kohm1_16W1%smd0402
SW1 SW2 = 2W_Switch_Pushbuttonsmd
U2 U22 U26 U39 U47 U97 = SN74LVC1G07DCKRE4
U48 U49 U84 = TPD1E10B06DPYR
U71 U98 = SN74LVC1G08DCKR
Y1 = 1Y_Crystal20MHzSCM
C146 = 1C_4700pFCapacitor50V10%0402
C149 C154 C156 C159 C161 C163 C168 C175 C177 C180 C182 C184 C189 = 1C_10uFCapacitor16V10%0805
J4 = 2H_Header_5x1
J8 = 2J_ConnectorRJ45_10_100MbAMDIX
R116 R200 R201 R232 R235-R238 = 1R_2.2KOhmResistor1_16W0402
R218 R222 R278 R322 = 1R_ZeroOhmResistor1_16W0603
R224-R227 = 1R_49.9OhmResistor1_16W0402
R228 = 1R_4.87Kohm1_16W1%smd0402
U17 = TLK105LRHBR
C157 C158 C178 C179 = 1C_47uFCapacitor16V20%1206: DescriptiveText: Capacitor 47uF 10V Ceramic X5R 1206; Mfr: Murata; MfrNum: GRM31CR61A476ME15L; PartName: 47uF10V20%SMDX5R; TIIntPartnumber: 1C0152
C166 C167 C187 C188 = C1005X7R1H104K050BE: DescriptiveText: CAP, CER, 0.1UF, 50V, 10%, X7R, 0402; Mfr: TDK CORPORATION
C172 C173 C193 C194 = CGA2B2C0G1H180J050BA: DescriptiveText: CAP, CER, 18 PF, 50V, 5%, C0G, 0402; Mfr: TDK CORPORATION
D3 D4 = Diode200mA250V_0: TIIntPartnumber: _1E0013
FB1-FB8 = HF70ACB201209-T: DescriptiveText: FERRITE, CHIP BEAD, 10 OHM, 0805; Mfr: TDK
J10 J12 = 2J_ConnectorRJ45_Gigabit
Q7 Q8 = 1Q_MOSFET_PChan_FDT434P_1
R279 = RMCF0402JT1K50: DescriptiveText: RES, THICK FILM, 1.5K OHM, 5%, 0.063W, SMT0402; Mfr: STACKPOLE ELECTRONICS
R280 R324 = 1R_100KOhmResistor1_16W0402
R281-R292 R325-R336 = RMCF0402FT22R1: DescriptiveText: RES, THICK FILM, 22.1 OHM, 1%, 0.063W, SMT0402; Mfr: STACKPOLE ELECTRONICS
R293 R296 R337 R340 = 1R_220ohm1_10W1%smd0402
R297 R342 = 1R_4.7KOhmResistor1_16W0402
R298 R341 = 1R_12.1KohmResistor1_16W1%0402
R304 R317 R319 R321 R348 R361 R363 = 1R_1KOhmResistor1_16W0402
R310 R313 R315 R354 R357 R359 = 1R_33ohmResistor1_16W5%0402
TP16 TP17 TP19 TP22 TP23 = 2H_Testpoint_SMD1mmCircle
U21 U24 = KSZ9031RNXCC
U23 U25 = 1A_CDCE913
Y3 Y4 = 1Y_Crystal25MHzABM3_0
C212 = 1C_4.7uFCapacitor16V10%0603
J15 = 2C_Conn_microSD_8
J44 = 2H_Header_0
R408 = 470Kohm1_16W1%SMD0402
U30 = TPD6E001RSER
U1 = AM5749ABZXEA: DescriptiveText: Dual Cortex A15 Dual C66X SOC AM574x
C1_1 C2_1 = 1C_1uFCapacitor50V10%0603: DNI: DNI
C246 C247 = 1C_15pFCapacitor50V10%smd0402
J1_1 = 2H_Header_4x1_female: DNI: DNI
R1_1 = 1R_ZeroOhmResistor1_16W0603: DNI: DNI
R2_1 = RMCF0402FT10K0: DNI: DNI; DescriptiveText: RES, THICK FILM,10K OHM, 1%, 0.063W, SMT0402; Mfr: STACKPOLE ELECTRONICS
TP1_1 = 2H_TestPointThroughHole: DNI: DNI
U1_1 = 1A_TLV70717: DNI: DNI; MfrNum: TLV70718DQN
Y6 = MC-306_32.7680K-A0: DescriptiveText: CRYSTAL, 32.7680KHZ, 12.5PF, SMD
C316 = 1C_1uFCapacitor50V10%0603
J21 = NPPN302AFCN-RC
Q16 = 1Q_MOSFET_NChan_BSS138_0
R113 = RMCF0402FT62R0: DescriptiveText: RES, THICK FILM, 62 OHM, 1%, 0.063W, SMT0402; Mfr: STACKPOLE ELECTRONICS
U18 = 1G_Haptics_Pico_0

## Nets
AGND_GBETH0: C166.2 C167.2 J10.SHLD1 J10.SHLD2
AGND_GBETH1: C187.2 C188.2 J12.SHLD1 J12.SHLD2
AGNDFRAME_PRU2ETH1: C146.2 J8.SHLD1 J8.SHLD2
DGND: C1_1.2 C2_1.2 C3.2 C4.2 C5.2 C140.2 C141.2 C142.2 C143.2 C144.2 C145.2 C146.1 C147.2 C148.2 C149.2 C150.2 C151.2 C153.2 C154.2 C155.2 C156.2 C157.2 C158.2 C159.2 C160.2 C161.2 C162.2 C163.2 C164.2 C165.2 C166.1 C167.1 C168.2 C169.2 C170.2 C171.2 C172.1 C173.1 C174.2 C175.2 C176.2 C177.2 C178.2 C179.2 C180.2 C181.2 C182.2 C183.2 C184.2 C185.2 C186.2 C187.1 C188.1 C189.2 C190.2 C191.2 C192.2 C193.1 C194.1 C211.2 C212.2 C213.2 C214.2 C246.2 C247.2 C248.2 C316.2 C569.2 C570.2 C571.2 J1_1.1 J4.5 J8.8 J10.1 J10.12 J10.13 J12.1 J12.12 J12.13 J15.6(VSS) J15.9(GND) J15.11(GND3) J15.12(GND4) J15.13(GND5) J15.14(GND6) J15.15(GND7) J15.16(GND8) J21.22 J21.39 J21.40 J21.59 J21.60 J44.2 Q16.S(SOURCE) R2_1.2 R13.2(P2) R116.1(P1) R228.1(P1) R235.1(P1) R236.1(P1) R237.1(P1) R238.1(P1) R298.2 R304.1(P1) R317.1(P1) R319.1(P1) R321.1(P1) R341.2 R348.1(P1) R361.1(P1) R363.1(P1) R569.2(P2) R643.2(P2) R793.1(P1) R923.2(P2) R924.2(P2) R925.2(P2) R927.1(P1) R928.1(P1) SW1.1 SW1.2 SW2.1 SW2.2 TP1_1.1 U1.AC14(VSSA_OSC1) U1_1.2(GND) U1_1.TPAD U2.3(GND) U17.TPAD U18.M1 U18.M2 U21.13(VSS_PS) U21.29(VSS) U21.49(P_GND) U22.3(GND) U23.5(GND1) U23.10(GND2) U24.13(VSS_PS) U24.29(VSS) U24.49(P_GND) U25.5(GND1) U25.10(GND2) U26.3(GND) U30.5(GND) U39.3(GND) U47.3(GND) U48.2 U49.2 U71.3(GND) U84.2 U97.3(GND) U98.3(GND) ; also on sheet 1 2 3 4 5 6 8 9 10 11 12 14 15 16 17 18 19 20 21 22 23 24 25 33 34
GND_OSC0: C1.2 C2.2 R13.1(P1) U1.AF15(VSSA_OSC0)
V1_8D: C1_1.1 C169.1 C190.1 R1_1.2(P2) U1_1.1(OUT) U23.3(VDD) U25.3(VDD) ; also on sheet 5 20 23 33
V1_8D_OUT: J1_1.2 R1_1.1(P1)
V3_3D: C2_1.1 C3.1 C143.1 C144.1 C145.1 C151.1 C170.1 C191.1 C211.1 C212.1 C214.1 C248.1 C569.1 C571.1 FB1.1 FB5.1 J1_1.3 J15.4(VDD) J21.1 R2.2 R8.2(P2) R10.2 R200.2(P2) R201.2(P2) R202.2(P2) R203.2(P2) R214.2(P2) R222.1(P1) R224.1(P1) R225.1(P1) R226.1(P1) R227.1(P1) R232.2(P2) R233.2 R278.2(P2) R322.2(P2) R498.2 R914.2 R917.2 U1_1.4(IN) U2.5(VCC) U17.21(VDD33_IO) U23.6(VDDOUT1) U23.7(VDDOUT2) U25.6(VDDOUT1) U25.7(VDDOUT2) U30.10(VCC) U39.2(A) U39.5(VCC) U47.5(VCC) U71.5(VCC) U97.5(VCC) U98.5(VCC) ; also on sheet 2 3 4 5 6 8 9 10 11 12 14 15 17 18 19 20 21 22 23 24 25 33 34
V3_3D_PRU2ETH1JCK: C140.1 C141.1 J8.3 J8.4 R202.1(P1)
V5_0D: J21.2 ; also on sheet 4 14 15 19 21
AM57XX_GPIO6_14: R685.2(P2) U1.E21(GPIO6_14)
AM57XX_GPIO6_15: R661.2(P2) U1.F20(GPIO6_15)
AM57XX_GPIO6_16: R666.2(P2) U1.F21(GPIO6_16)
AM57XX_GPMC_AD0: R861.2(P2) U1.M6(GPMC_AD0/GPIO) ; also on sheet 10
AM57XX_GPMC_AD1: R862.2(P2) U1.M2(GPMC_AD1/GPIO) ; also on sheet 10
AM57XX_GPMC_AD2: R863.2(P2) U1.L5(GPMC_AD2/GPIO) ; also on sheet 10
AM57XX_GPMC_AD3: R864.2(P2) U1.M1(GPMC_AD3/GPIO) ; also on sheet 10
AM57XX_GPMC_AD4: J21.51 U1.L6(GPMC_AD4/GPIO) ; also on sheet 10
AM57XX_GPMC_AD5: J21.53 U1.L4(GPMC_AD5/GPIO) ; also on sheet 10
AM57XX_GPMC_AD6: J21.55 U1.L3(GPMC_AD6/GPIO) ; also on sheet 10
AM57XX_GPMC_AD7: J21.57 U1.L2(GPMC_AD7/GPIO) ; also on sheet 10
AM57XX_GPMC_AD8: J21.32 U1.L1(GPMC_AD8) ; also on sheet 10
AM57XX_GPMC_AD9: J21.34 U1.K2(GPMC_AD9) ; also on sheet 10
AM57XX_GPMC_AD10: J21.36 U1.J1(GPMC_AD10) ; also on sheet 10
AM57XX_GPMC_AD11: J21.38 U1.J2(GPMC_AD11) ; also on sheet 10
AM57XX_GPMC_AD12: J21.42 U1.H1(GPMC_AD12) ; also on sheet 10
AM57XX_GPMC_AD13: J21.44 U1.J3(GPMC_AD13) ; also on sheet 10
AM57XX_GPMC_AD14: J21.46 U1.H2(GPMC_AD14) ; also on sheet 10
AM57XX_GPMC_AD15: J21.48 U1.H3(GPMC_AD15) ; also on sheet 10
AM57XX_INDETHER_LED0_GRN: R803.2(P2) ; also on sheet 34
AM57XX_INDETHER_LED0_RED: U1.B26(XREF_CLK2) ; also on sheet 34
AM57XX_INDETHER_LED0_YEL: U1.D15(MCASP2_AXR4) ; also on sheet 34
AM57XX_INDETHER_LED1_GRN: U1.B17(MCASP2_AXR6) ; also on sheet 34
AM57XX_INDETHER_LED1_RED: U1.B16(MCASP2_AXR5) ; also on sheet 34
AM57XX_INDETHER_LED1_YEL: U1.A17(MCASP2_AXR7) ; also on sheet 34
AM57XX_INDETHER_LED2_GRN: U1.F16(SPI1_D1) ; also on sheet 34
AM57XX_INDETHER_LED2_RED: U1.B25(SPI1_D0) ; also on sheet 34
AM57XX_INDETHER_LED2_YEL: U1.A24(SPI1_CS0) ; also on sheet 34
AM57XX_INDETHER_LED3_GRN: U1.AF6(VIN1A_D13) ; also on sheet 34
AM57XX_INDETHER_LED3_RED: U1.A22(SPI1_CS1) ; also on sheet 34
AM57XX_INDETHER_LED3_YEL: U1.AF3(VIN1A_D14) ; also on sheet 34
AM57XX_MCASP1_AXR4: R673.2(P2) U1.E12(MCASP1_AXR4)
AM57XX_MCASP1_AXR5: R674.2(P2) U1.F13(MCASP1_AXR5)
AM57XX_MCASP1_AXR6: R675.2(P2) U1.C12(MCASP1_AXR6)
AM57XX_MCASP1_AXR7: R676.2(P2) U1.D12(MCASP1_AXR7)
AM57XX_MMC1_CLK: R405.2(P2) U1.W6(MMC1_CLK)
AM57XX_MMC1_CMD: R404.2(P2) U1.Y6(MMC1_CMD)
AM57XX_MMC1_DAT0: R406.2(P2) U1.AA6(MMC1_DAT0)
AM57XX_MMC1_DAT1: R407.2(P2) U1.Y4(MMC1_DAT1)
AM57XX_MMC1_DAT2: R402.2(P2) U1.AA5(MMC1_DAT2)
AM57XX_MMC1_DAT3: R403.2(P2) U1.Y3(MMC1_DAT3)
AM57XX_MMC1_SDCD: R409.2(P2) U1.W7(MMC1_SDCD)
AM57XX_MMC1_SDWP: J44.1 R644.1 U1.Y9(MMC1_SDWP)
AM57XX_OSC0_IN: C2.1 R4.2(P2) U1.AE15(XI_OSC0) Y1.3
AM57XX_OSC0_OUT: R5.1(P1) U1.AD15(XO_OSC0)
AM57XX_PORZn: R6.1(P1) U1.F22(PORZ)
AM57XX_PR1_UART0_RXD: J21.47 ; also on sheet 12
AM57XX_PR1_UART0_TXD: J21.45 ; also on sheet 12 17
AM57XX_PR2_PROFI_TXEN: J21.49 ; also on sheet 12
AM57XX_PRU1ETH1_MRCLK: R332.2 U1.C3(VIN2A_D14/RGMII1_TXD3) ; also on sheet 24
AM57XX_PRU1ETH1_TXCLK: R746.2(P2) ; also on sheet 24
AM57XX_PRU1ETH1_TXD0: R326.2 U1.C2(VIN2A_D13/RGMII1_TXCTL) ; also on sheet 24
AM57XX_PRU1ETH1_TXD1: R325.2 U1.D5(VIN2A_D12/RGMII1_TXC) ; also on sheet 24
AM57XX_PRU1ETH1_TXD3: R747.2(P2) ; also on sheet 24
AM57XX_PRU1ETH_MDCLK: R748.2(P2) ; also on sheet 22 24
AM57XX_PRU2ETH1_MRCLK: R209.2(P2) U1.AC9(MMC3_DAT2/PR2_MII_MR1_CLK)
AM57XX_PRU2ETH1_RXD0: R213.2(P2) U1.AB5(MMC3_DAT7/PR2_MII1_RXD0)
AM57XX_PRU2ETH1_RXD1: R215.2(P2) U1.AB8(MMC3_DAT6/PR2_MII1_RXD1)
AM57XX_PRU2ETH1_RXD2: R216.2(P2) U1.AD6(MMC3_DAT5/PR2_MII1_RXD2)
AM57XX_PRU2ETH1_RXD3: R217.2(P2) U1.AC8(MMC3_DAT4/PR2_MII1_RXD3)
AM57XX_PRU2ETH1_RXDV: R211.2(P2) U1.AC3(MMC3_DAT3/PR2_MII1_RXDV)
AM57XX_PRU2ETH1_RXER: R212.2(P2) U1.B19(MCASP3_AXR0/PR2_MII1_RXER)
AM57XX_PRU2ETH1_TXCLK: R204.2(P2) U1.AC5(GPIO6_10/PR2_MII_MT1_CLK)
AM57XX_PRU2ETH1_TXD0: R206.2(P2) U1.AC6(MMC3_DAT1/PR2_MII1_TXD0)
AM57XX_PRU2ETH1_TXD1: R208.2(P2) U1.AC7(MMC3_DAT0/PR2_MII1_TXD1)
AM57XX_PRU2ETH1_TXD2: R210.2(P2) U1.AC4(MMC3_CMD/PR2_MII1_TXD2)
AM57XX_PRU2ETH1_TXD3: R207.2(P2) U1.AD4(MMC3_CLK/PR2_MII1_TXD3)
AM57XX_PRU2ETH1_TXEN: R205.2(P2) U1.AB4(GPIO6_11/PR2_MII1_TXEN)
AM57XX_PRU2ETH_MDCLK: R221.2(P2) ; also on sheet 17
AM57XX_PRU2ETH_MDDATA: R223.2(P2) ; also on sheet 17
AM57XX_RGMII0_RD0: R289.2 U1.W2(RGMII0_RXD0) ; also on sheet 22
AM57XX_RGMII0_RD1: R290.2 U1.Y2(RGMII0_RXD1) ; also on sheet 22
AM57XX_RGMII0_RD2: R291.2 U1.V3(RGMII0_RXD2) ; also on sheet 22
AM57XX_RGMII0_RD3: R292.2 U1.V4(RGMII0_RXD3) ; also on sheet 22
AM57XX_RGMII0_RXCLK: R288.2 U1.U5(RGMII0_RXC) ; also on sheet 22
AM57XX_RGMII0_RXCTL: R285.2 U1.V5(RGMII0_RXCTL) ; also on sheet 22
AM57XX_RGMII0_TD0: R282.2 U1.U6(RGMII0_TXD0) ; also on sheet 22
AM57XX_RGMII0_TD1: R287.2 U1.V6(RGMII0_TXD1) ; also on sheet 22
AM57XX_RGMII0_TD2: R283.2 U1.U7(RGMII0_TXD2) ; also on sheet 22
AM57XX_RGMII0_TD3: R284.2 U1.V7(RGMII0_TXD3) ; also on sheet 22
AM57XX_RGMII0_TXCLK: R281.2 U1.W9(RGMII0_TXC) ; also on sheet 22
AM57XX_RGMII0_TXCTL: R286.2 U1.V9(RGMII0_TXCTL) ; also on sheet 22
AM57XX_RGMII1_RD0: R333.2 U1.A4(VIN2A_D23/RGMII1_RXD0) ; also on sheet 24
AM57XX_RGMII1_RD1: R334.2 U1.B5(VIN2A_D22/RGMII1_RXD1) ; also on sheet 24
AM57XX_RGMII1_RD2: R335.2 U1.B4(VIN2A_D21/RGMII1_RXD2) ; also on sheet 24
AM57XX_RGMII1_RD3: R336.2 U1.B3(VIN2A_D20/RGMII1_RXD3) ; also on sheet 24
AM57XX_RGMII1_RXCLK: R328.2 U1.C5(VIN2A_D18/RGMII1_RXC) ; also on sheet 24
AM57XX_RGMII1_RXCTL: R329.2 U1.A3(VIN2A_D19/RGMII1_RXCTL) ; also on sheet 24
AM57XX_RGMII1_TD0: R330.2 U1.D6(VIN2A_D17/RGMII1_TXD0) ; also on sheet 24
AM57XX_RGMII1_TD1: R331.2 U1.B2(VIN2A_D16/RGMII1_TXD1) ; also on sheet 24
AM57XX_RGMII1_TD2: R327.2 U1.C4(VIN2A_D15/RGMII1_TXD2) ; also on sheet 24
AM57XX_RSTOUTn: R36.2(P2) R922.2(P2) U1.F23(RSTOUTn) U47.2(A)
AM57XX_SPI2_SCLK: R684.1(P1) U1.A26(SPI2_SCLK)
AM57XX_STATUSLED0_GRN: R736.2(P2) ; also on sheet 34
AM57XX_STATUSLED0_RED: R735.2(P2) ; also on sheet 34
AM57XX_STATUSLED0_YEL: R737.2(P2) ; also on sheet 34
AM57XX_STATUSLED1_GRN: R739.2(P2) ; also on sheet 34
AM57XX_STATUSLED1_RED: R738.2(P2) ; also on sheet 34
AM57XX_STATUSLED1_YEL: R740.2(P2) ; also on sheet 34
AM57XX_VIN2A_CLK0: R669.1(P1) U1.E1(VIN2A_CLK0)
AM57XX_VIN2A_DE0: R119.2(P2) R670.1(P1) U1.G2(VIN2A_DE0)
AM57XX_VIN2A_FLD0: R671.1(P1) U1.H7(VIN2A_FLD0)
AM57XX_VIN2A_HSYNC0: R118.2(P2) R672.1(P1) U1.G1(VIN2A_HSYNC0)
AM57XX_VIN2A_VSYNC0: R735.1(P1) U1.G6(VIN2A_VSYNC0) ; also on sheet 17
AM57XX_VOUT1_FLD: R564.1(P1) U1.B11(VOUT1_FLD)
AM572X_HAPTICS_TRIG: R114.1(P1) U1.A25(SPI1_SCLK)
AM572X_HDMI_DDC_SCL: R358.2(P2) ; also on sheet 4
AM572X_HDMI_DDC_SDA: R356.2(P2) ; also on sheet 4
CAM_ENn: R685.1(P1) ; also on sheet 11
CAN1_RXDF: J21.41 ; also on sheet 8
CAN1_TXDF: J21.43 ; also on sheet 8
eMMC_RSTn: R564.2(P2) ; also on sheet 6
ETH0_LDO_O: Q7.G(GATE) U21.43(LDO_O)
ETH0_MDC: R294.1(P1) U21.36(MDC)
ETH0_MDIO: R295.1(P1) U21.37(MDIO)
ETH0_RXCLK: R288.1 R317.2(P2) U21.35(RX_CLK)
ETH0_RXD0: R289.1 R299.2 U21.32(RXD0)
ETH0_RXD1: R290.1 R301.2 U21.31(RXD1)
ETH0_RXD2: R291.1 R306.2 U21.28(RXD2)
ETH0_RXD3: R292.1 R309.2 U21.27(RXD3)
ETH0_RXDV: R285.1 R304.2(P2) U21.33(RX_DV)
ETH0_TXCLK: R281.1 U21.24(GTX_CLK)
ETH0_TXD0: R282.1 U21.19(TXD0)
ETH0_TXD1: R287.1 U21.20(TXD1)
ETH0_TXD2: R283.1 U21.21(TXD2)
ETH0_TXD3: R284.1 U21.22(TXD3)
ETH0_TXEN: R286.1 U21.25(TX_EN)
ETH0GB_25MHzCLK: R315.2 U21.46(XI)
ETH1_LDO_O: Q8.G(GATE) U24.43(LDO_O)
ETH1_MDC: R338.1(P1) U24.36(MDC)
ETH1_MDIO: R339.1(P1) U24.37(MDIO)
ETH1_RESETn: C189.1 D4.2(Anode) R324.1(P1) U24.42(RESET_N) U26.4(Y)
ETH1_RXCLK: R328.1 R361.2(P2) U24.35(RX_CLK)
ETH1_RXD0: R333.1 R343.2 U24.32(RXD0)
ETH1_RXD1: R334.1 R345.2 U24.31(RXD1)
ETH1_RXD2: R335.1 R352.2 U24.28(RXD2)
ETH1_RXD3: R336.1 R353.2 U24.27(RXD3)
ETH1_RXDV: R329.1 R348.2(P2) U24.33(RX_DV)
ETH1_TXCLK: R325.1 U24.24(GTX_CLK)
ETH1_TXD0: R330.1 U24.19(TXD0)
ETH1_TXD1: R331.1 U24.20(TXD1)
ETH1_TXD2: R327.1 U24.21(TXD2)
ETH1_TXD3: R332.1 U24.22(TXD3)
ETH1_TXEN: R326.1 U24.25(TX_EN)
ETH1GB_25MHzCLK: R359.2 U24.46(XI)
ETH_MDIO_CLK: R294.2(P2) R338.2(P2) U1.V1(MDIO_MCLK) ; also on sheet 22
ETH_MDIO_DATA: R279.1 R295.2(P2) R339.2(P2) U1.U4(MDIO_D) ; also on sheet 22
ETHER0_D0N: J10.10 U21.3(TXRXM_A)
ETHER0_D0P: J10.9 U21.2(TXRXP_A)
ETHER0_D1N: J10.8 U21.6(TXRXM_B)
ETHER0_D1P: J10.7 U21.5(TXRXP_B)
ETHER0_D2N: J10.6 U21.8(TXRXM_C)
ETHER0_D2P: J10.5 U21.7(TXRXP_C)
ETHER0_D3N: J10.4 U21.11(TXRXM_D)
ETHER0_D3P: J10.3 U21.10(TXRXP_D)
ETHER1_D0N: J12.10 U24.3(TXRXM_A)
ETHER1_D0P: J12.9 U24.2(TXRXP_A)
ETHER1_D1N: J12.8 U24.6(TXRXM_B)
ETHER1_D1P: J12.7 U24.5(TXRXP_B)
ETHER1_D2N: J12.6 U24.8(TXRXM_C)
ETHER1_D2P: J12.5 U24.7(TXRXP_C)
ETHER1_D3N: J12.4 U24.11(TXRXM_D)
ETHER1_D3P: J12.3 U24.10(TXRXP_D)
GB_ETH0_INTn: R297.1(P1) R662.1(P1) U21.38(INT_N_/_PME_N2)
GB_ETH1_INTn: R342.1(P1) R663.1(P1) U24.38(INT_N_/_PME_N2)
GBETH0_RESETn: C168.1 D3.2(Anode) R280.1(P1) U21.42(RESET_N) U22.4(Y)
GPIO_PCIE_RSTDRVn: R659.1(P1) ; also on sheet 18
GPIO_PCIE_SWRSTn: R660.1(P1) ; also on sheet 18
GPIO_PRU1_ETH0_RESETn: R673.1(P1) ; also on sheet 22
GPIO_PRU1_ETH1_RESETn: R674.1(P1) ; also on sheet 24
GPIO_PRU2_ETH0_RESETn: R675.1(P1) ; also on sheet 17
GPIO_PRU2_ETH1_RESETn: R234.2(P2) R676.1(P1)
GPIO_TOUCH_RESETn: R661.1(P1) ; also on sheet 5
GPIO_USB2_VBUS_DET: R809.1(P1) ; also on sheet 20
GPIO_VPP_PWR_EN: U1.AE3(VIN1A_D17) ; also on sheet 23
GPMC_CLK: J21.58 R689.1(P1)
GPMC_CS0: J21.4 R686.1(P1)
GPMC_CS3: J21.6 R688.1(P1)
HAPTICS_N: Q16.D(DRAIN) U18.2(N-)
HAPTICS_P: C316.1 R113.1 U18.1(P+)
HDQ: J21.50 ; also on sheet 11
IND_I2C_SCL: J21.27 R314.2(P2) ; also on sheet 5 10 11 18 20 21
IND_I2C_SDA: J21.29 R312.2(P2) ; also on sheet 5 10 11 18 20 21
MMC_CD: J15.10(CD) R408.1(P1) R409.1(P1) U84.1
MMC_CLK: J15.5(CLOCK) R405.1(P1) U30.1(IO1)
MMC_CMD: J15.3(CMD) R398.1 R404.1(P1) U30.7(IO5)
MMC_D0: J15.7(DAT0) R399.1 R406.1(P1) U30.2(IO2)
MMC_D1: J15.8(DAT1) R400.1 R407.1(P1) U30.3(IO3)
MMC_D2: J15.1(DAT2) R401.1 R402.1(P1) U30.6(IO4)
MMC_D3: J15.2(CD/DAT3) R397.1 R403.1(P1) U30.8(IO6)
OSC0_OUT: C1.1 R4.1(P1) R5.2(P2) Y1.1
PCIE_CRDPRESENT: R664.1(P1) ; also on sheet 18
PCIE_RESETn: R919.1(P1) R920.1(P1) ; also on sheet 18
PCIE_WAKEn: R665.1(P1) ; also on sheet 18
PHY0_LED_ACTn: R293.1 R321.2(P2) U21.17(LED1_/_PME_N1)
PHY0_LED_LINKn: R296.1 R319.2(P2) U21.15(LED2)
PHY1_LED_ACTn: R337.1 R364.2 U24.17(LED1_/_PME_N1)
PHY1_LED_LINKn: R340.1 R363.2(P2) U24.15(LED2)
PHY_RESETn: R915.1(P1) R921.1(P1) U22.2(A) U26.2(A) U71.2(B) ; also on sheet 17 22 24
PMIC_EN: R645.1 R928.2(P2) R929.1(P1) ; also on sheet 20
PMIC_INT: R666.1(P1) ; also on sheet 20
PMIC_RESET_OUTn: R9.1(P1) ; also on sheet 20
PORZn: C213.1 R6.2(P2) R499.1(P1) R920.2(P2) R921.2(P2) R926.1(P1) U98.4(Y)
PR1_EDC_LATCH0: R743.2(P2) U1.E2(VIN2A_D3)
PR1_EDC_SYNC0: R744.2(P2) U1.D2(VIN2A_D4)
PR1_EDIO_DATA_OUT1: J4.4 R119.1(P1)
PR1_EDIO_DATA_OUT3: J4.3 R118.1(P1)
PR2_EDC_LATCH0: J21.13 R748.1(P1) ; also on sheet 5
PR2_EDC_LATCH1: J21.15 R749.1(P1) ; also on sheet 5
PR2_EDC_SYNC0: J21.17 R750.1(P1) ; also on sheet 5
PR2_EDC_SYNC1: J21.19 R751.1(P1) ; also on sheet 5
PR2_MII1_RXDV: J4.2 R117.1(P1)
PR2_MII1_TXEN: J4.1 R115.1(P1)
PR2_UART0_RXD: J21.54 ; also on sheet 5
PR2_UART0_TXD: J21.56 ; also on sheet 5
PRU1ETH0_25MHzCLK: R310.2 ; also on sheet 22
PRU1ETH0_INTn: R669.2(P2) ; also on sheet 22
PRU1ETH1_25MHzCLK: R313.2 ; also on sheet 24
PRU1ETH1_INTn: R670.2(P2) ; also on sheet 24
PRU1ETH1_RXCLK: R750.2(P2) ; also on sheet 24
PRU1ETH1_RXD1: R752.2(P2) ; also on sheet 24
PRU1ETH1_RXD3: R751.2(P2) ; also on sheet 24
PRU1ETH1_RXERR: R753.2(P2) ; also on sheet 24
PRU1ETH1_TXD1: R749.2(P2) ; also on sheet 24
PRU2ETH0_25MHzCLK: R354.2 ; also on sheet 17
PRU2ETH0_INTn: R671.2(P2) ; also on sheet 17
PRU2ETH1_25MHzCLK: R357.2 U17.23(XI)
PRU2ETH1_COL: R220.1(P1) R231.1(P1) R232.1(P1) U17.29(COL)
PRU2ETH1_CRS: R219.1(P1) U17.27(CRS)
PRU2ETH1_INTn: R672.2(P2) U17.8(PWRDNn/INTn)
PRU2ETH1_LINKLED: R200.1(P1) R218.2(P2) U17.17(LED_LINK)
PRU2ETH1_MDC: R221.1(P1) U17.20(MDC)
PRU2ETH1_MDIO: R201.1(P1) R223.1(P1) U17.19(MDIO)
PRU2ETH1_RESETn: U17.18(RESET_N) U71.4(Y)
PRU2ETH1_RXCLK: R209.1(P1) U17.25(RX_CLK)
PRU2ETH1_RXD0: R213.1(P1) R238.2(P2) U17.30(RXD_0)
PRU2ETH1_RXD1: R215.1(P1) R237.2(P2) U17.31(RXD_1)
PRU2ETH1_RXD2: R216.1(P1) R236.2(P2) U17.32(RXD_2)
PRU2ETH1_RXD3: R217.1(P1) R235.2(P2) U17.1(RXD_3)
PRU2ETH1_RXDV: R117.2(P2) R211.1(P1) U17.26(RX_DV)
PRU2ETH1_RXERR: R212.1(P1) U17.28(RX_ERR)
PRU2ETH1_TXCLK: R204.1(P1) U17.2(TX_CLK)
PRU2ETH1_TXD0: R206.1(P1) U17.4(TXD_0)
PRU2ETH1_TXD1: R208.1(P1) U17.5(TXD_1)
PRU2ETH1_TXD2: R210.1(P1) U17.6(TXD_2)
PRU2ETH1_TXD3: R207.1(P1) U17.7(TXD_3)
PRU2ETH1_TXEN: R115.2(P2) R205.1(P1) U17.3(TX_EN)
PRU2ETHER1_RDN: J8.6 R224.2(P2) U17.9(RD-)
PRU2ETHER1_RDP: J8.5 R225.2(P2) U17.10(RD+)
PRU2ETHER1_TDN: J8.2 R226.2(P2) U17.11(TD-)
PRU2ETHER1_TDP: J8.1 R227.2(P2) U17.12(TD+)
RSTOUTTOPMIC: R36.1(P1) R793.2(P2) ; also on sheet 20
SPI2_CS0n: J21.30 U1.B24(SPI2_CS0)
SPI2_DIN: J21.26 U1.G17(SPI2_D0)
SPI2_DOUT: J21.28 U1.B22(SPI2_D1)
SPI2_SCLK: J21.24 R684.2(P2)
SYS_RESETn: J21.25 R918.1(P1) R922.1(P1) ; also on sheet 5 25
SYS_WARMRESETn: C570.1 R2.1 R7.2(P2) R915.2(P2) R918.2(P2) R919.2(P2) U47.4(Y) U97.4(Y) ; also on sheet 2 10
TOUCH_INT: R802.2(P2) ; also on sheet 5
VADD33_PRU2ETH1: C142.1 R222.2(P2) U17.14(AVDD33)
VETH0_AVDDH: C153.1 C154.1 C157.1 FB1.2 Q7.S(SOURCE) U21.1(AVDDH) U21.12(AVDDH) U21.47(AVDDH)
VETH0_AVDDL: C161.1 C162.1 FB4.2 U21.4(AVDDL) U21.9(AVDDL)
VETH0_AVDDL_PLL: C163.1 C164.1 C165.1 FB2.2 U21.44(AVDDL_PLL)
VETH0_AVDDL_PMOS: C158.1 FB2.1 FB3.1 FB4.1 Q7.D1(DRAIN1) Q7.D2(DRAIN2)
VETH0_DVDDH: C155.1 C156.1 C171.1 D3.1(Cathode) R278.1(P1) R279.2 R280.2(P2) R297.2(P2) R299.1 R301.1 R306.1 R309.1 U21.16(DVDDH) U21.34(DVDDH) U21.40(DVDDH) U22.5(VCC)
VETH0_DVDDL: C159.1 C160.1 FB3.2 U21.14(DVDDL) U21.18(DVDDL) U21.23(DVDDL) U21.26(DVDDL) U21.30(DVDDL) U21.39(DVDDL)
VETH1_AVDDH: C176.1 C177.1 C178.1 FB5.2 Q8.S(SOURCE) U24.1(AVDDH) U24.12(AVDDH) U24.47(AVDDH)
VETH1_AVDDL: C182.1 C183.1 FB8.2 U24.4(AVDDL) U24.9(AVDDL)
VETH1_AVDDL_PLL: C184.1 C185.1 C186.1 FB6.2 U24.44(AVDDL_PLL)
VETH1_AVDDL_PMOS: C179.1 FB6.1 FB7.1 FB8.1 Q8.D1(DRAIN1) Q8.D2(DRAIN2)
VETH1_DVDDH: C174.1 C175.1 C192.1 D4.1(Cathode) R322.1(P1) R324.2(P2) R342.2(P2) R343.1 R345.1 R352.1 R353.1 R364.1 U24.16(DVDDH) U24.34(DVDDH) U24.40(DVDDH) U26.5(VCC)
VETH1_DVDDL: C180.1 C181.1 FB7.2 U24.14(DVDDL) U24.18(DVDDL) U24.23(DVDDL) U24.26(DVDDL) U24.30(DVDDL) U24.39(DVDDL)
VMAIN: R113.2 ; also on sheet 5 11 19 20
VPP_EN: J1_1.4 R2_1.1 U1_1.3(EN)
VRTC_OUT: R645.2 ; also on sheet 20 23
VSDMMC: R397.2 R398.2 R399.2 R400.2 R401.2 R408.2(P2) R644.2 ; also on sheet 20 23 33
N10692191: R11.2(P2) SW2.3 SW2.4 U48.1
N10692247: C5.1 R11.1(P1) R914.1 U97.2(A)
N12123192: J10.11 R293.2
N12123204: J10.14 R296.2
N12138943: R298.1 U21.48(ISET)
N12139138: TP16.1 U21.41(CLK125_NDO)
N17120040: J21.3 R743.1(P1)
N17120055: J21.5 R744.1(P1)
N17120061: J21.9 R746.1(P1)
N17120072: J21.11 R747.1(P1)
N17120087: J21.21 R752.1(P1)
N17120090: J21.23 R753.1(P1)
N17156111: C172.2 R305.2(P2) U23.1(Xin/CLK) Y3.2
N17156113: C173.2 R305.1(P1) R308.2(P2) Y3.1
N17156222: R308.1(P1) U23.14(XOUT)
N17156522: R310.1 U23.11(Y1)
N17156525: R313.1 U23.9(Y2)
N17156528: R315.1 U23.8(Y3)
N17156983: R314.1(P1) U23.12(S2/SCL)
N17156986: R312.1(P1) U23.13(S1/SDA)
N17569906: J12.11 R337.2
N17569909: J12.14 R340.2
N17569918: R341.1 U24.48(ISET)
N17569921: TP17.1 U24.41(CLK125_NDO)
N17570093: C193.2 R349.2(P2) U25.1(Xin/CLK) Y4.2
N17570094: C194.2 R349.1(P1) R351.2(P2) Y4.1
N17570107: R351.1(P1) U25.14(XOUT)
N17570112: R354.1 U25.11(Y1)
N17570113: R357.1 U25.9(Y2)
N17570114: R359.1 U25.8(Y3)
N17570122: R358.1(P1) U25.12(S2/SCL)
N17570123: R356.1(P1) U25.13(S1/SDA)
N17596821: J8.11 R203.1(P1)
N17596823: C147.1 C148.1 C149.1 C150.1 U17.13(PFBIN1) U17.15(PFBOUT) U17.24(PFBIN2)
N17596838: J8.10 R230.1(P1) R231.2(P2)
N17596842: R220.2(P2) U1.D18(XREF_CLK0/PR2_MII1_COL)
N17596847: R230.2(P2) U1.C17(MCASP3_AXR1/PR2_MII1_RXLINK)
N17596886: J8.9 R214.1(P1)
N17596899: R233.1 R234.1(P1) U71.1(A)
N17596973: R219.2(P2) U1.E17(XREF_CLK1/PR2_MII1_CRS)
N17596976: R228.2(P2) U17.16(RBIAS)
N17596979: J8.12 R218.1(P1)
N18733248: R497.1(P1) U1.AD14(RTC_OSC_XO)
N18733249: C247.1 R497.2(P2) Y6.4
N18733252: C246.1 R927.2(P2) U1.AE14(RTC_OSC_XI) Y6.1
N18733262: R499.2(P2) U1.AF14(RTC_ISO)
N18733263: R498.1 R500.1(P1) U39.4(Y)
N18733273: R500.2(P2) R926.2(P2) U1.AB17(RTC_PORZ)
N18733274: R929.2(P2) U1.Y11(ON_OFF)
N18733276: R923.1(P1) TP19.1 U1.AD17(WAKEUP0)
N19425975: R7.1(P1) U1.E23(RESETn)
N19426030: R8.1(P1) U1.D21(NMI_DSP)
N19426454: R569.1(P1) U1.AC15(XI_OSC1)
N20204523: R643.1(P1) U1.AC17(WAKEUP1)
N20631200: Q16.G(GATE) R114.2(P2) R116.2(P2)
N20825141: R690.2(P2) U1.N1(GPMC_ADVN_ALE)
N20825143: R691.2(P2) U1.M5(GPMC_OEN_REN)
N20825145: R692.2(P2) U1.M3(GPMC_WEN)
N20825147: R732.2(P2) U1.N6(GPMC_BEN0)
N20825149: R733.2(P2) U1.M4(GPMC_BEN1)
N20825151: R734.2(P2) U1.N2(GPMC_WAIT0)
N21013400: R662.2(P2) U1.B14(MCASP1_ACLKR)
N21013403: R663.2(P2) U1.J14(MCASP1_FSR)
N21013406: R664.2(P2) U1.G13(MCASP1_AXR2)
N21013409: R665.2(P2) U1.J11(MCASP1_AXR3)
N21036279: J21.8 R690.1(P1)
N21036281: J21.10 R691.1(P1)
N21036293: J21.12 R692.1(P1)
N21036295: J21.14 R732.1(P1)
N21036304: J21.16 R733.1(P1)
N21036390: R686.2(P2) U1.T1(GPMC_CS0)
N21036392: R688.2(P2) U1.P1(GPMC_CS3/GPIO)
N21036394: R689.2(P2) U1.P7(GPMC_CLK)
N21036619: J21.52 R734.1(P1)
N21180149: TP22.1 U1.B15(MCASP2_AXR0)
N21180152: TP23.1 U1.A15(MCASP2_AXR1)
N21877717: R659.2(P2) U1.AE5(VIN1A_D18)
N21877759: R660.2(P2) U1.AE1(VIN1A_D19)
N21905162: R802.1(P1) U1.AG3(VIN1A_D10)
N21905296: R803.1(P1) U1.AH5(VIN1A_D5)
N22373548: R809.2(P2) U1.AD2(VIN1A_D22)
N22427447: R739.1(P1) U1.C26(UART1_TXD/GPIO)
N22427459: R740.1(P1) U1.B27(UART1_RXD/GPIO)
N22729003: J21.31 R861.1(P1)
N22729012: J21.33 R862.1(P1)
N22729021: J21.35 R863.1(P1)
N22729030: J21.37 R864.1(P1)
N22729576: R738.1(P1) U1.AG6(VIN1A_D6)
N22730116: R737.1(P1) U1.AG4(VIN1A_D8)
N22730128: R736.1(P1) U1.AH4(VIN1A_D7)
N22734288: R917.1 U2.4(Y) U98.2(B)
N22734327: C4.1 R10.1 R916.1(P1) U2.2(A)
N22734777: R916.2(P2) SW1.3 SW1.4 U49.1
N22735118: R9.2(P2) U98.1(A)
N22762383: R925.1(P1) U1.AC16(WAKEUP3)
N22762388: R924.1(P1) U1.AB16(WAKEUP2)

Not connected (* = marked no-connect by the designer): J8 7*; J10 2; J12 2*; J21 7* 18* 20*; U1 A20(MCASP2_FSR)* AA1(MLBP_DAT_P)* AA2(MLBP_DAT_N)* AA4(MCASP5_AXR1/GPIO)* AB1(MLBP_CLK_P)* AB2(MLBP_CLK_N)* AB3(MCASP5_AXR0/GPIO)* AC1(MLBP_SIG_P)* AC2(MLBP_SIG_N)* AC13(XO_OSC1)* AD3(VIN1A_D23)* AD8(VIN1A_D1)* AD9(VIN1A_DE0)* AE2(VIN1A_D20)* AE6(VIN1A_D21)* AE8(VIN1A_D0)* AE9(VIN1A_HSYNC0)* AF1(VIN1A_D16)* AF8(VIN1A_VSYNC0)* AF9(VIN1A_FLD0)* AG2(VIN1A_D9)* AG5(VIN1A_D11)* AG7(VIN1A_D2)* AG8(VIN1A_CLK0)* AG9(SATA1_RXP0)* AG10(SATA1_TXN0)* AG11(PCIE_RXN1)* AG12(PCIE_TXN1)* AH3(VIN1A_D4)* AH6(VIN1A_D3)* AH7(VIN1B_CLK1)* AH9(SATA1_RXN0)* AH10(SATA1_TXP0)* AH11(PCIE_RXP1)* AH12(PCIE_TXP1)* C27(UART1_RTSn/GPIO)* E15(MCASP2_ACLKR)* E25(UART1_CTSn/GPIO)* G16(MCASP4_AXR0/SPI3_D0)*; U2 1(NC)*; U17 22(XO)*; U21 45(XO); U22 1(NC)*; U23 2(S0)* 4(Vctr)*; U24 45(XO); U25 2(S0)* 4(Vctr)*; U26 1(NC)*; U30 4(NC1)* 9(NC2)*; U39 1(NC)*; U47 1(NC)*; U97 1(NC)*; Y1 2(NC0)* 4(NC1)*; Y6 2* 3*

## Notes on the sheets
sheet 27
- Note: MDIO Address = 0x01
- Real-Time Development
  Header
sheet 29
- SD/MMC1 Connector
sheet 30
- Catalog Processors - Vpp Programming Circuit
sheet 31
- Expansion Connector
sheet 32
- User Warm Reset Switch
